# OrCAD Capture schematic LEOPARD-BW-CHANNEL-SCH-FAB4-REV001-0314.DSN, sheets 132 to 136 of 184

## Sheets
132 031_CPU1 - PCIE (2A-2D): size A3; title: CPU0 - PCIE (2A-2D); note: LEOPARD MAIN BOARD
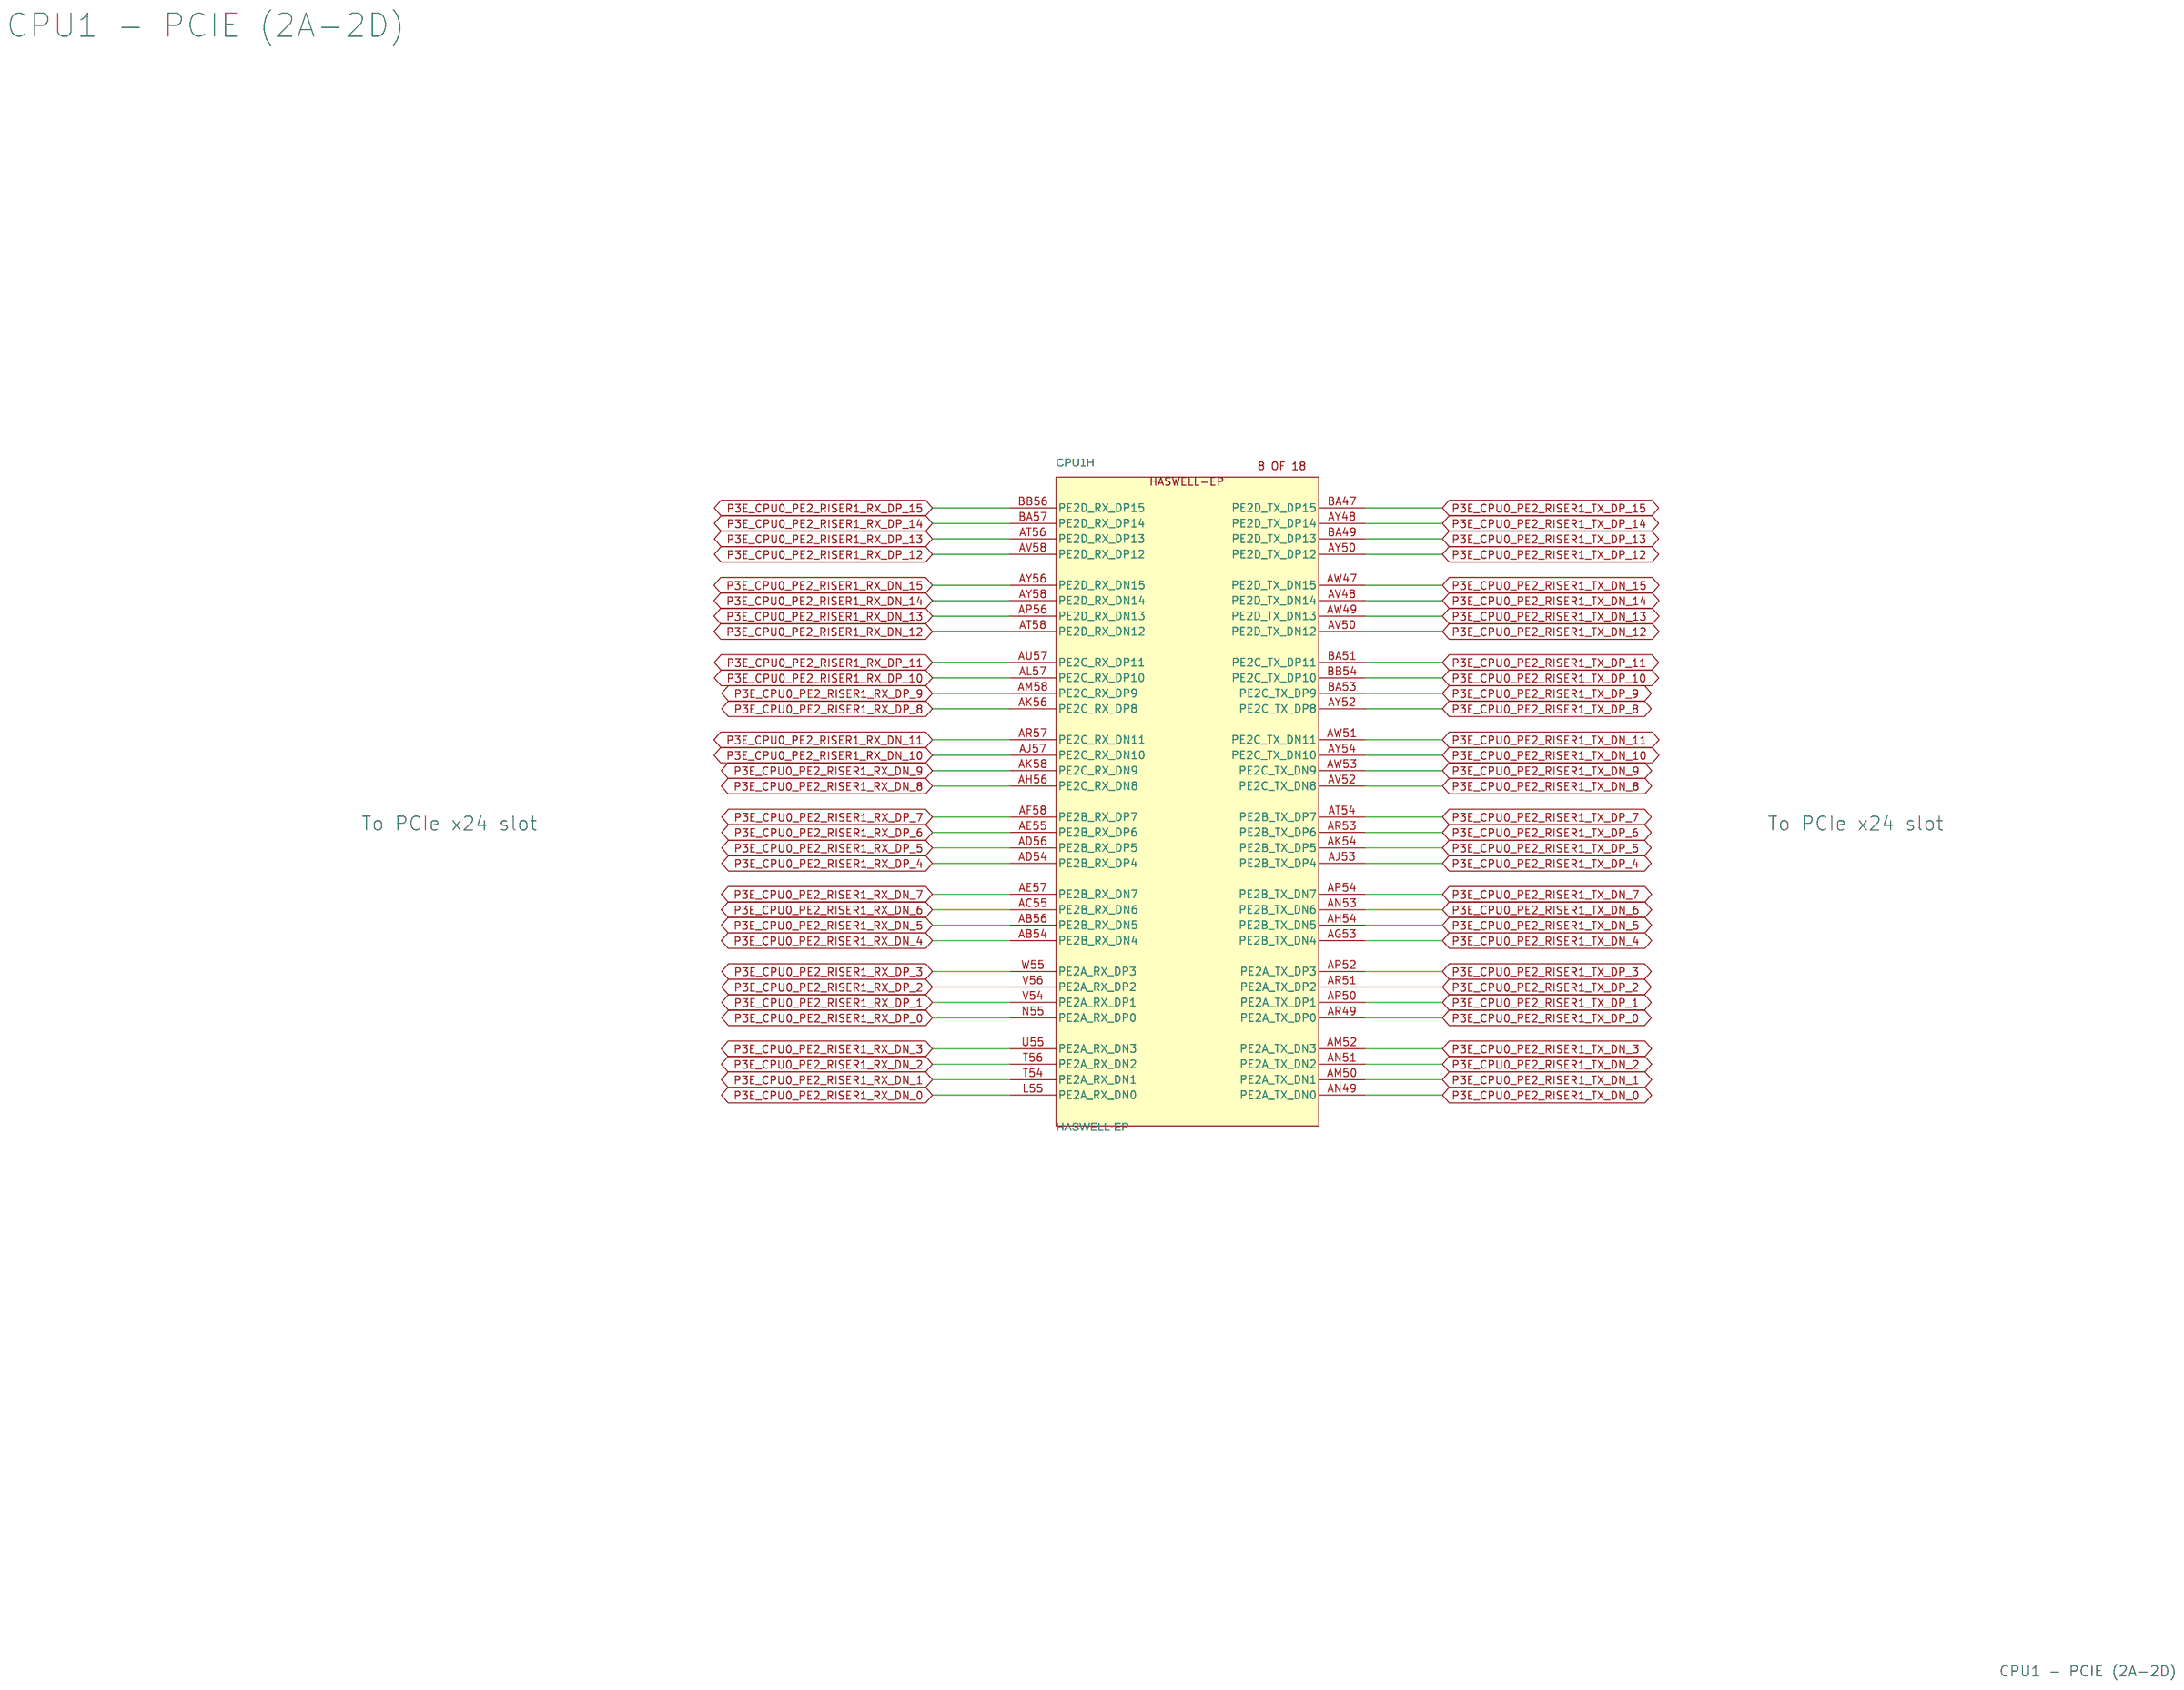
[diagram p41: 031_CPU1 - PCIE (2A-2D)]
133 030_CPU1 - DMI & PCIE (1A-1B): size A3; title: CPU1 - DMI & PCIE (1A-1B)
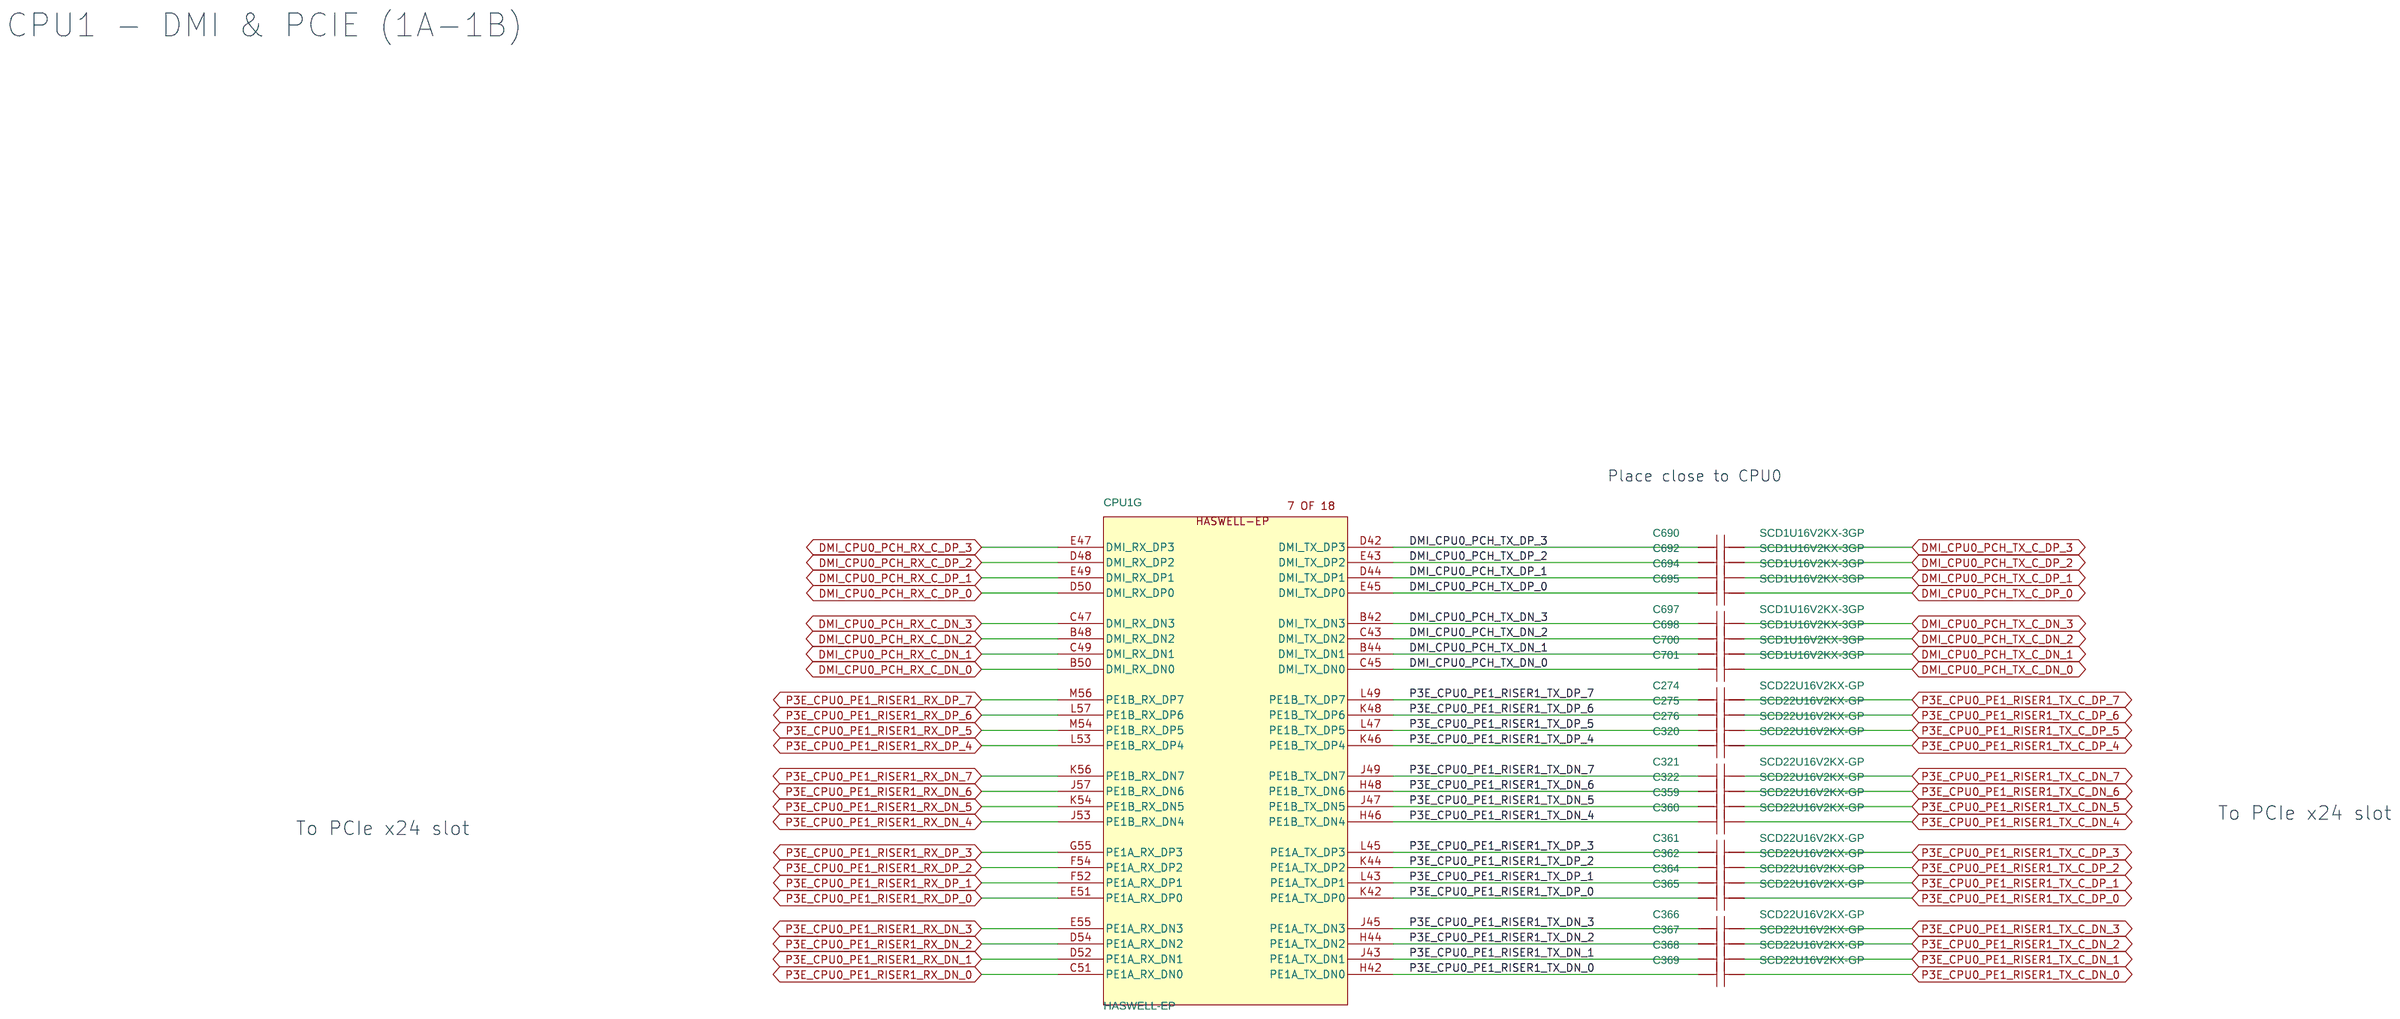
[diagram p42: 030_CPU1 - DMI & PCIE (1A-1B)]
134 029_CPU1 - DDR4 (CHANNEL D): size A3; title: CPU0 - DDR4 (CHANNEL D)
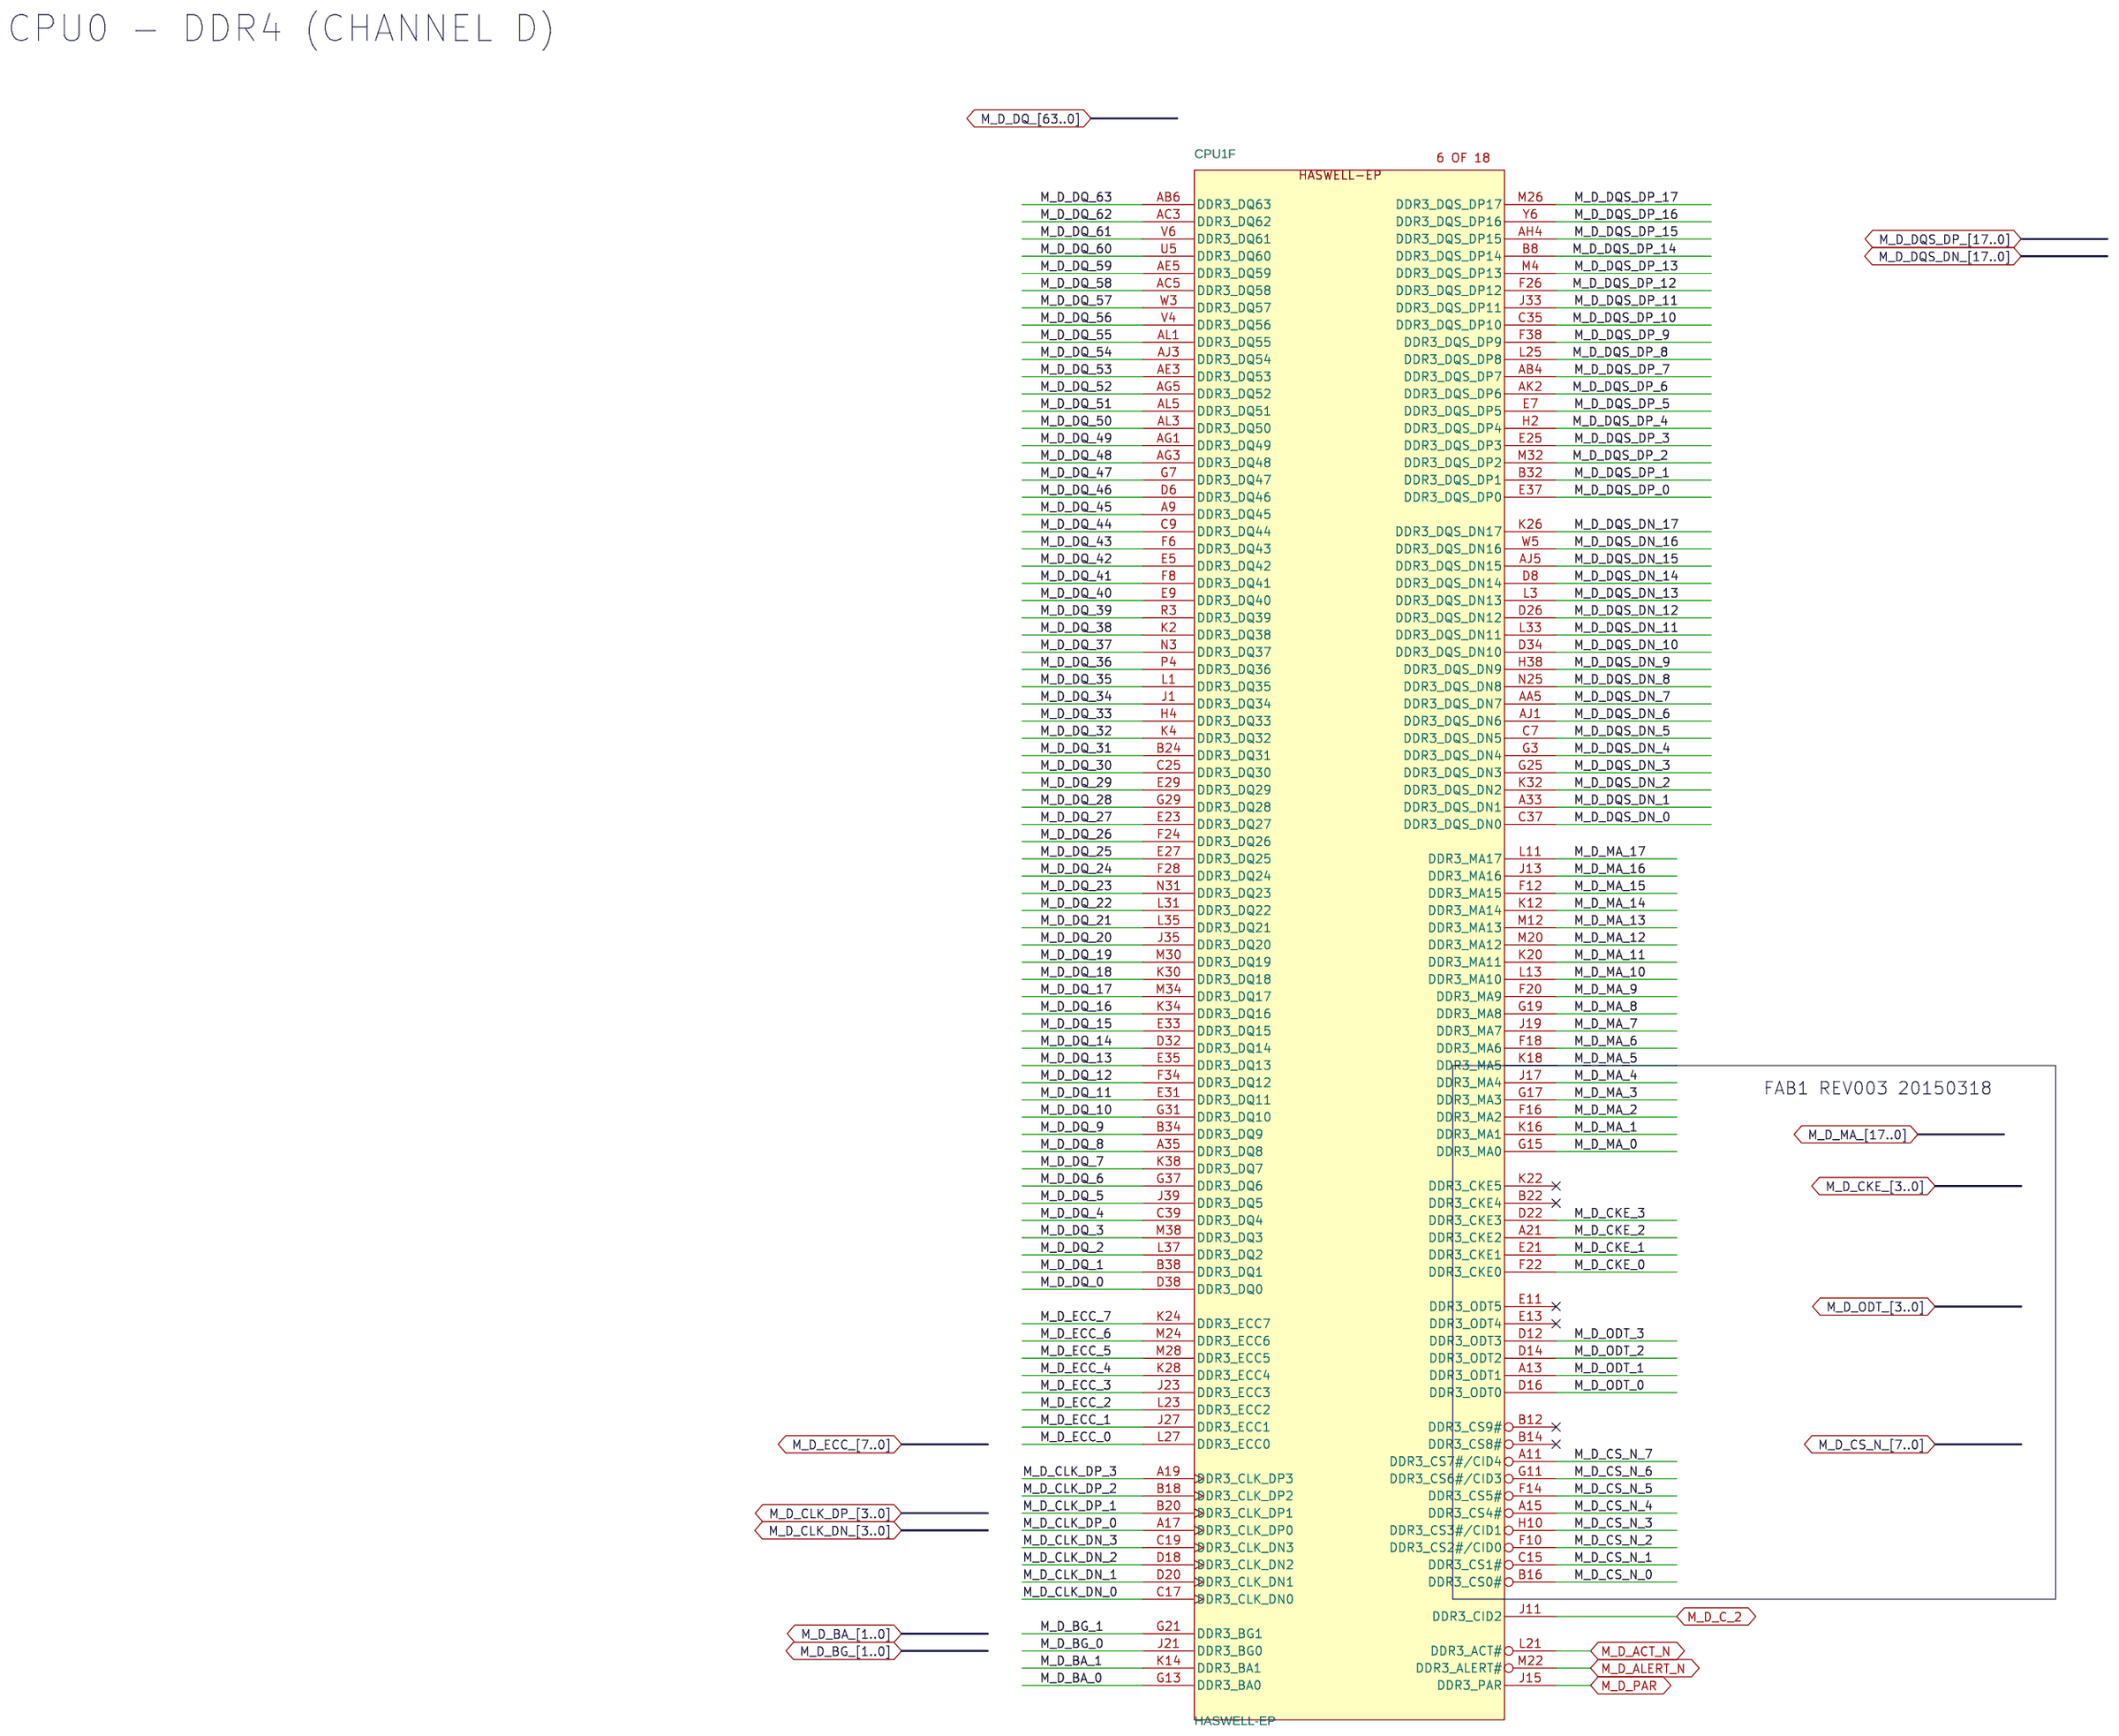
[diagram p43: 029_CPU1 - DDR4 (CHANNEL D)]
135 028_CPU1 - DDR4 (CHANNEL C): size A3; title: CPU1 - DDR4 (CAHANNEL C)
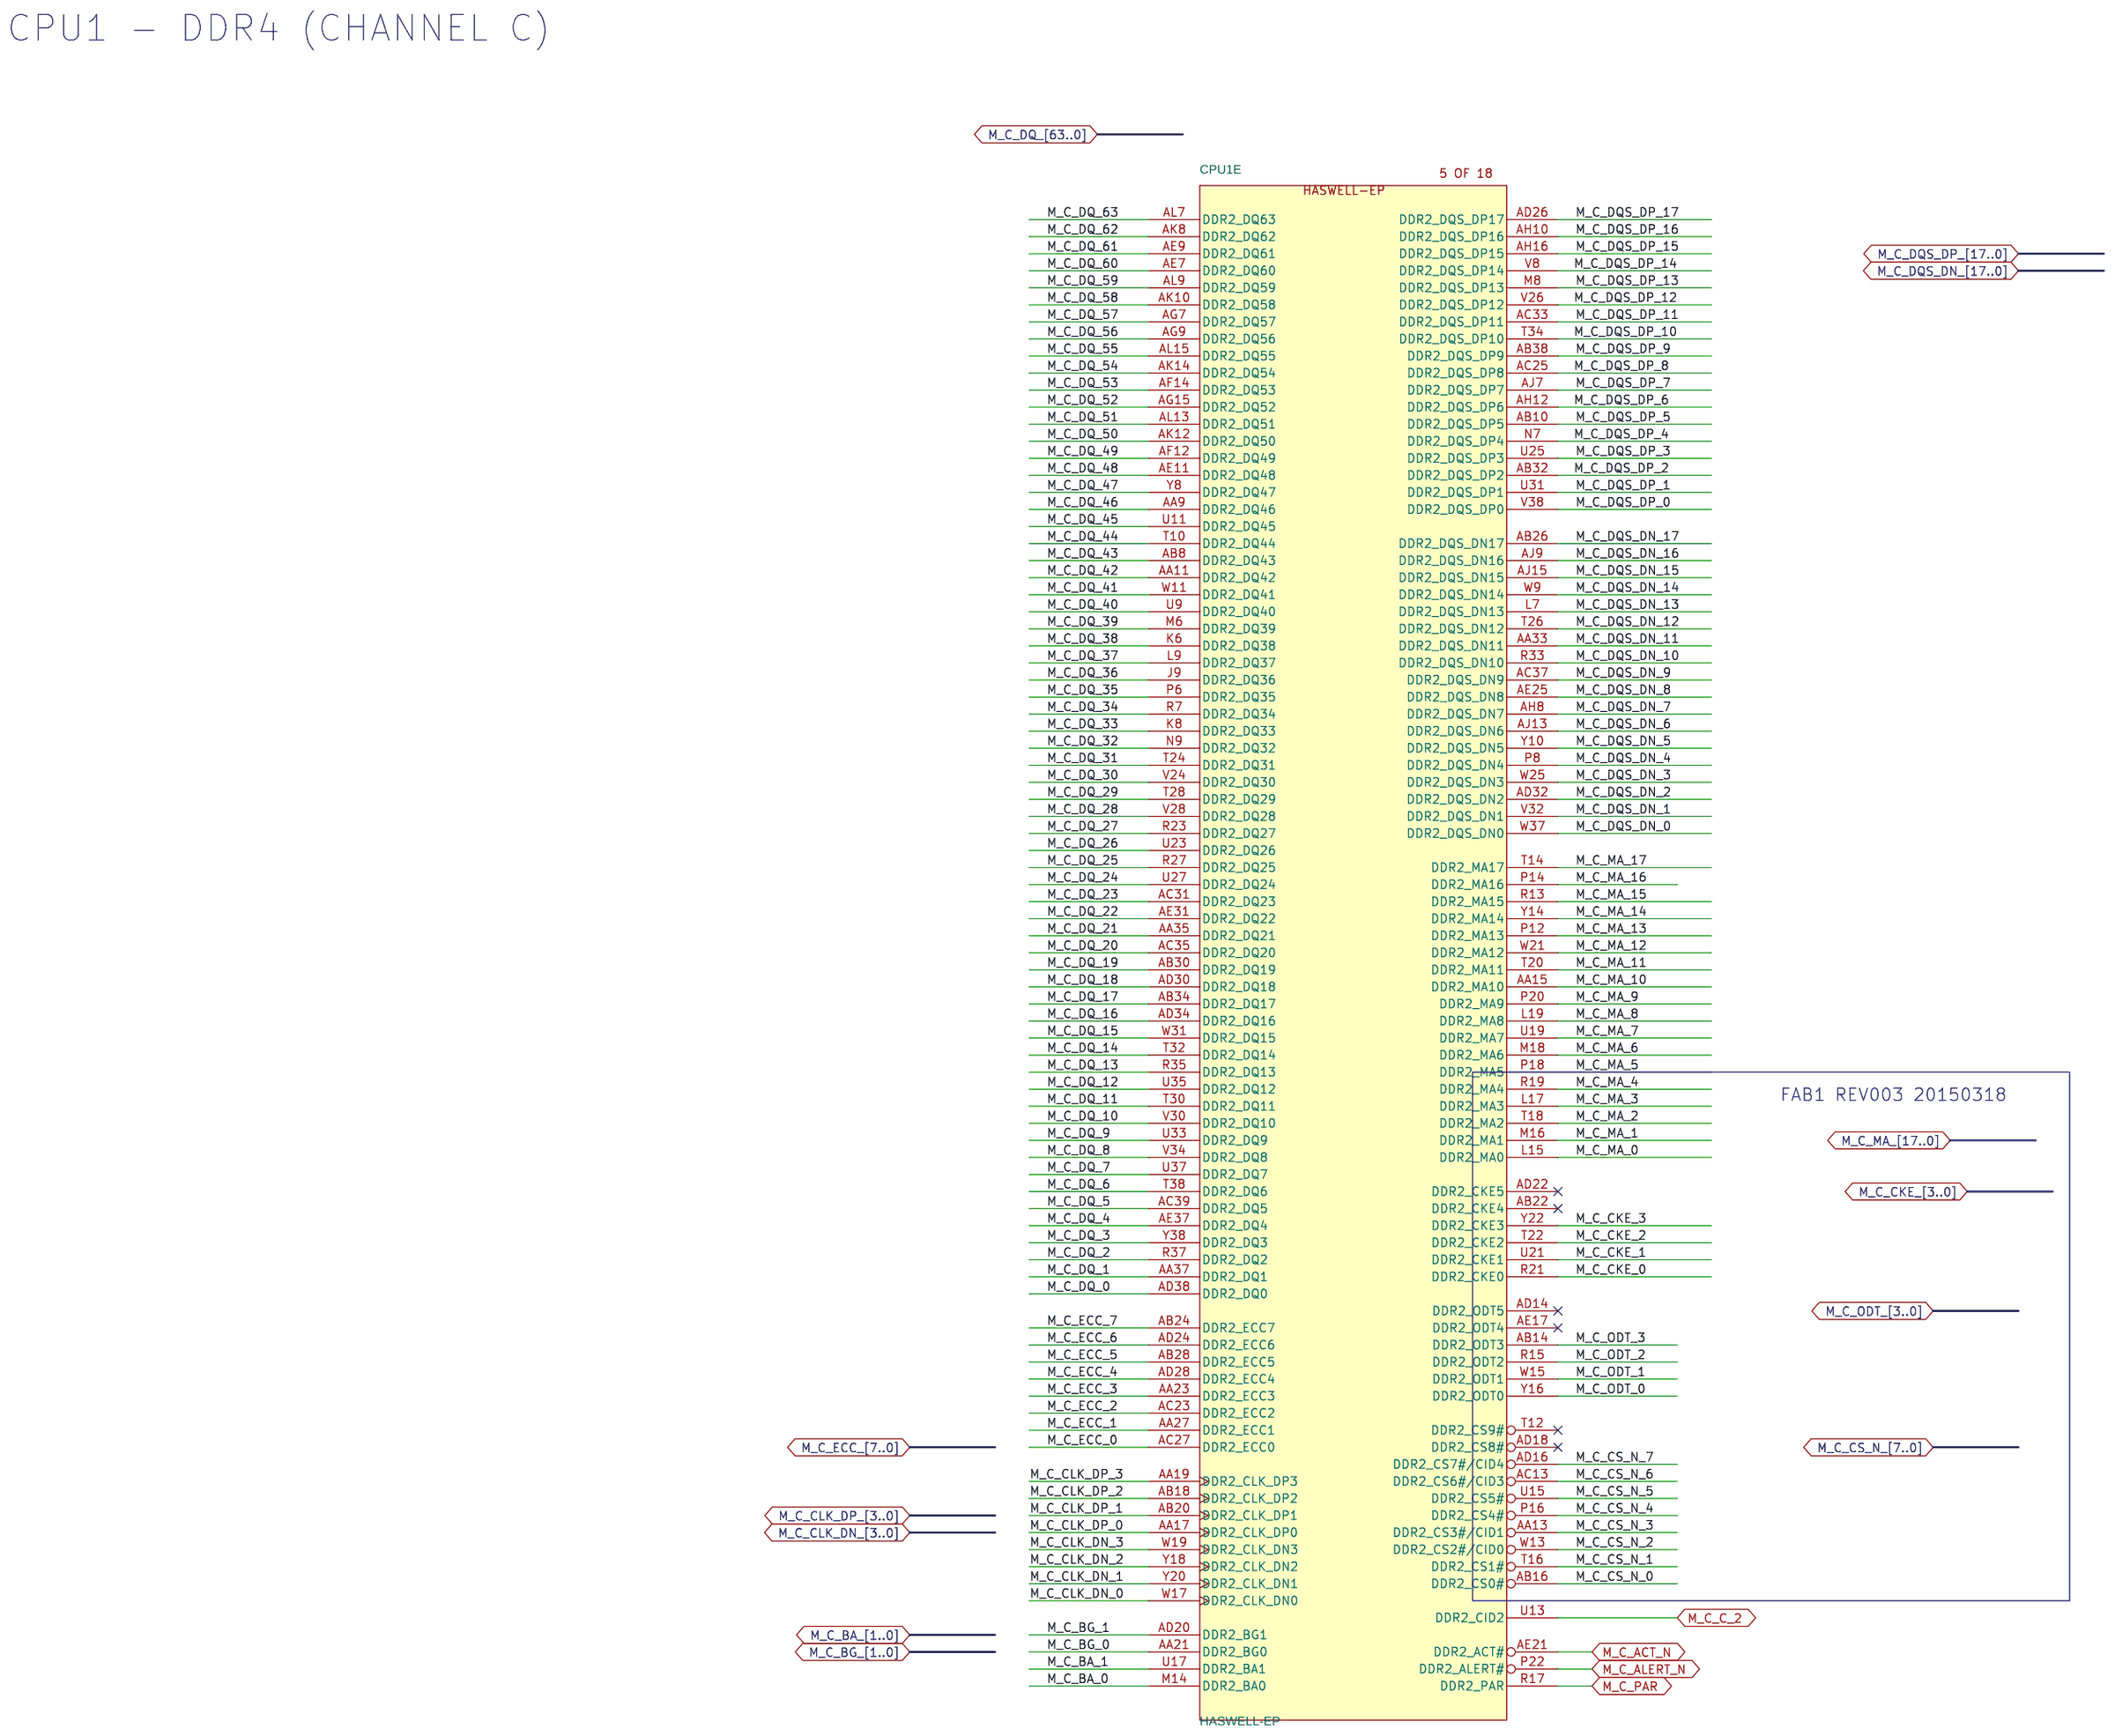
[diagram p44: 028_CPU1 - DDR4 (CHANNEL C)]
136 027_CPU1 - DDR4 (CHANNEL B): size A3; title: CPU0 - DDR4 (CHANNEL B)
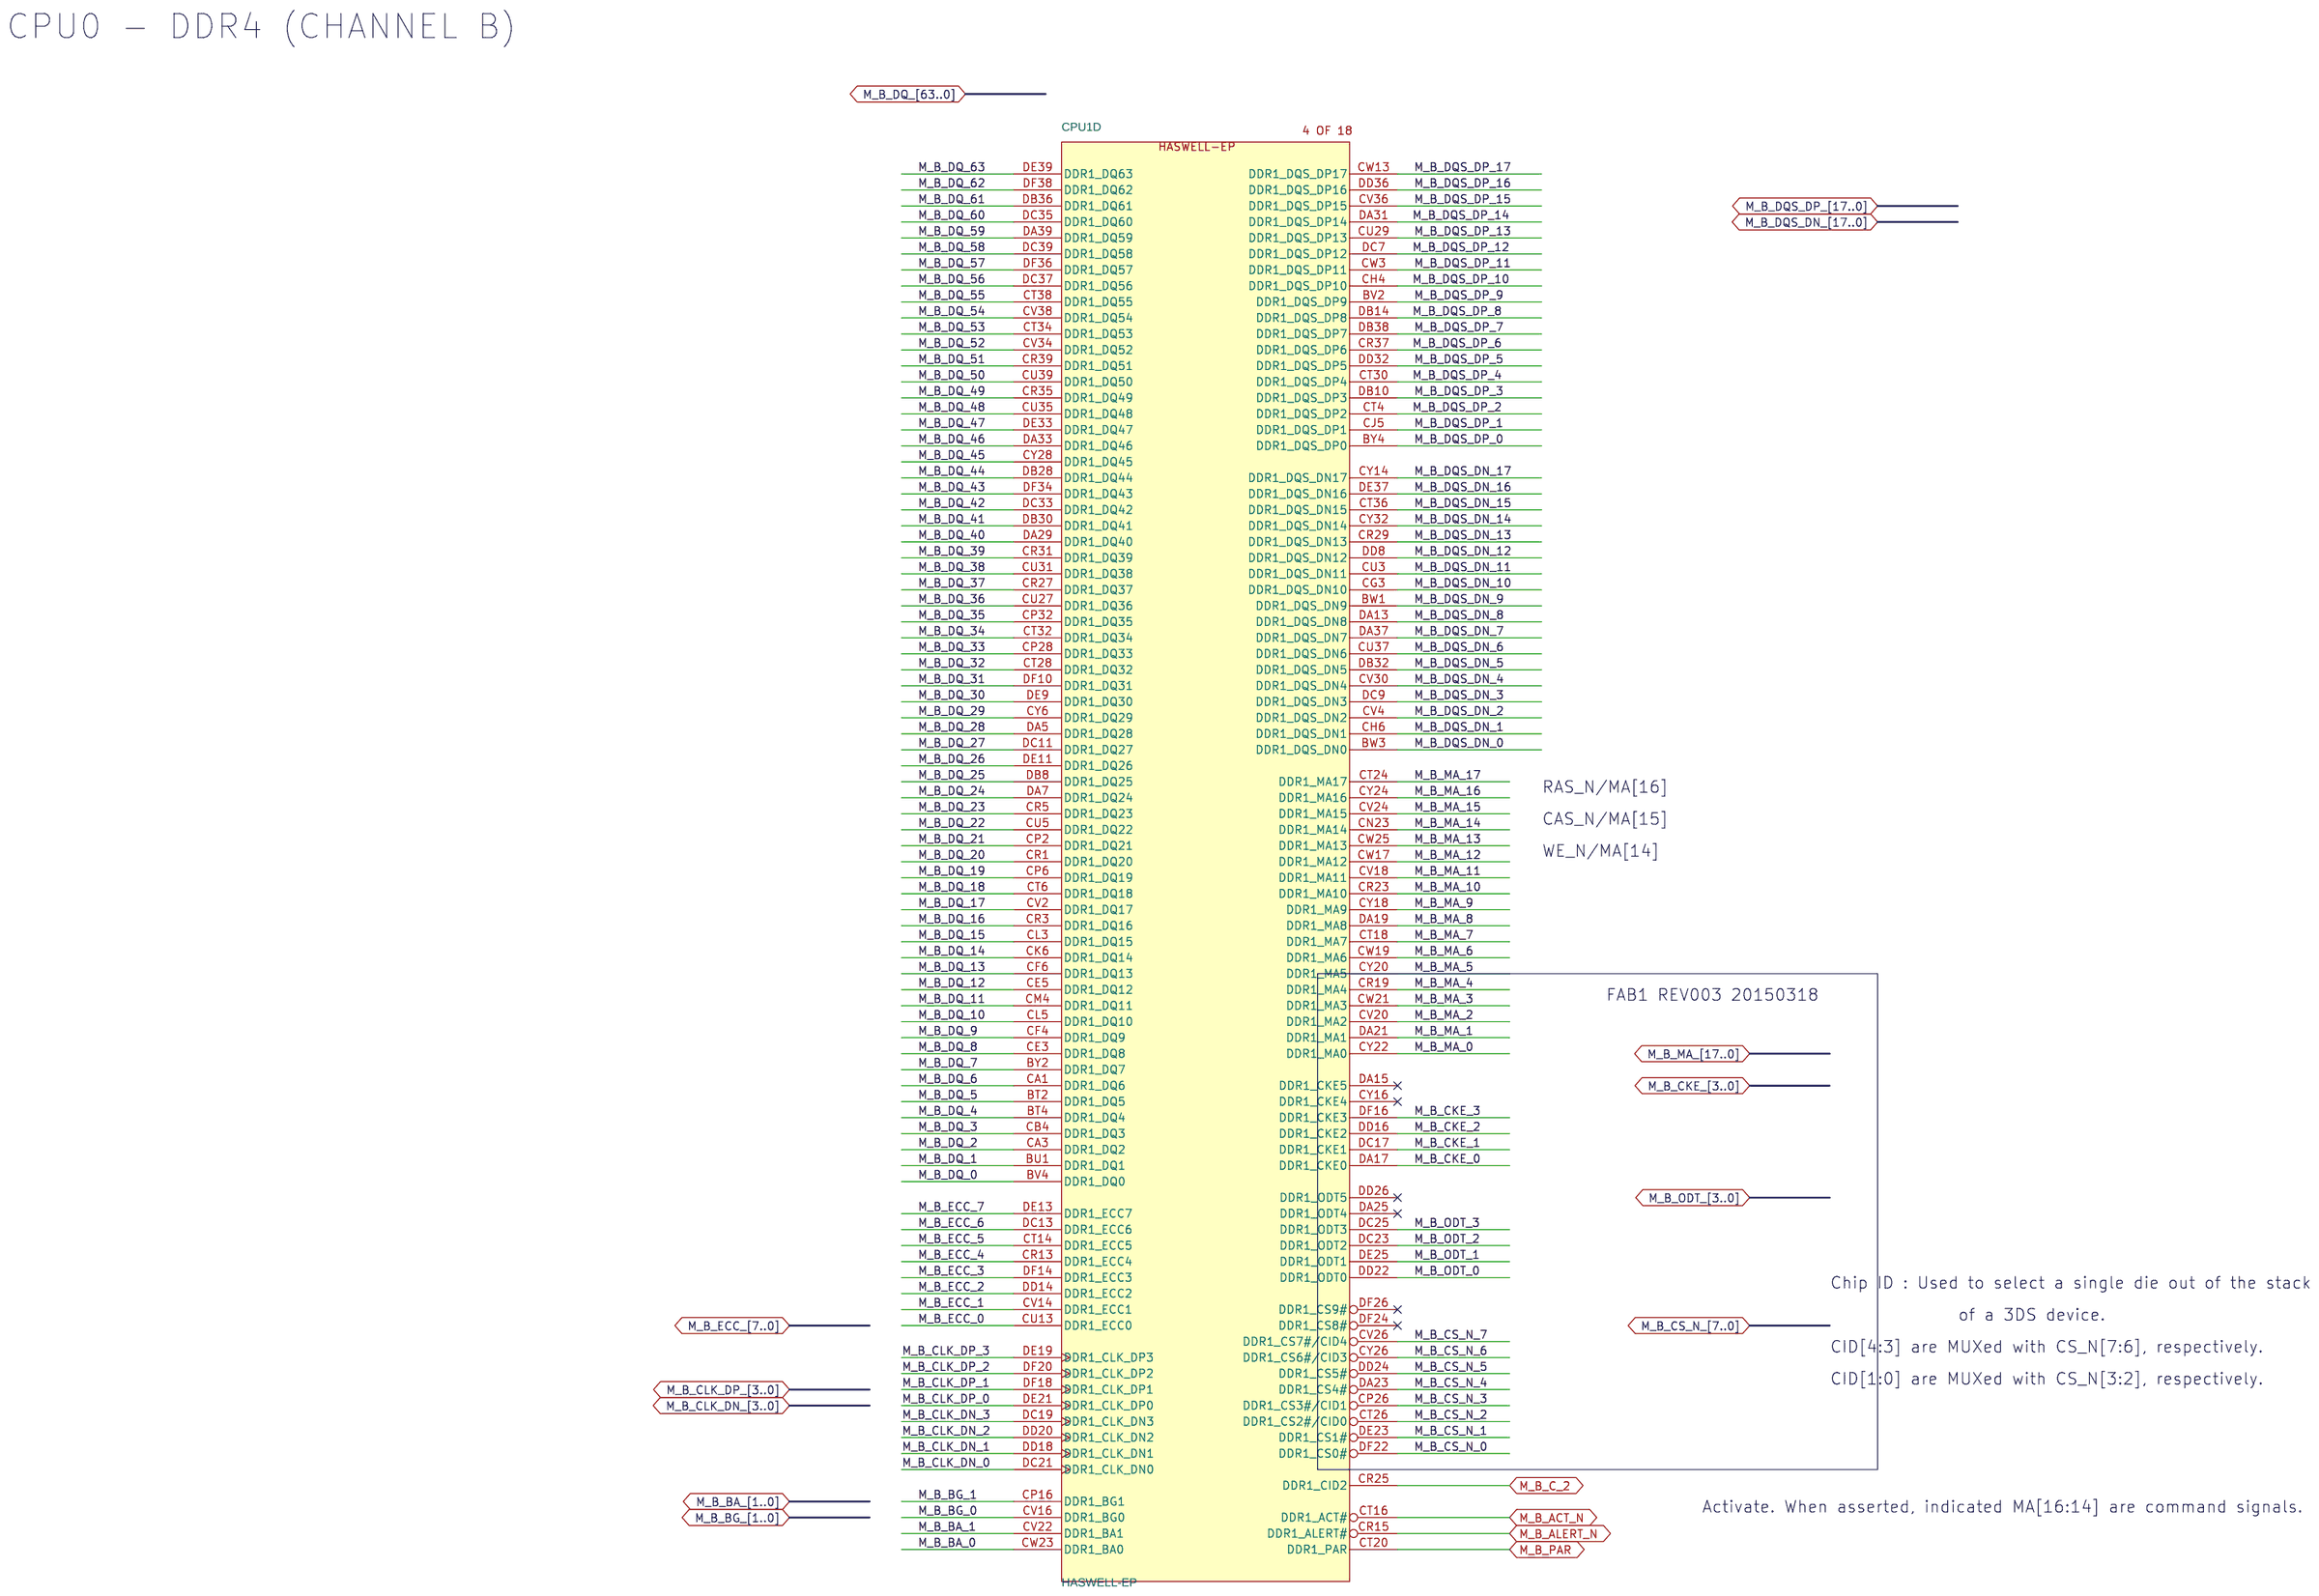
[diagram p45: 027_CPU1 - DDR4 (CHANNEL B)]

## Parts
sheet 030_CPU1 - DMI & PCIE (1A-1B)
C274  SCD22U16V2KX-GP  [C402H22]
C275  SCD22U16V2KX-GP  [C402H22]
C276  SCD22U16V2KX-GP  [C402H22]
C320  SCD22U16V2KX-GP  [C402H22]
C321  SCD22U16V2KX-GP  [C402H22]
C322  SCD22U16V2KX-GP  [C402H22]
C359  SCD22U16V2KX-GP  [C402H22]
C360  SCD22U16V2KX-GP  [C402H22]
C361  SCD22U16V2KX-GP  [C402H22]
C362  SCD22U16V2KX-GP  [C402H22]
C364  SCD22U16V2KX-GP  [C402H22]
C365  SCD22U16V2KX-GP  [C402H22]
C366  SCD22U16V2KX-GP  [C402H22]
C367  SCD22U16V2KX-GP  [C402H22]
C368  SCD22U16V2KX-GP  [C402H22]
C369  SCD22U16V2KX-GP  [C402H22]
C690  SCD1U16V2KX-3GP  [C402H22]
C692  SCD1U16V2KX-3GP  [C402H22]
C694  SCD1U16V2KX-3GP  [C402H22]
C695  SCD1U16V2KX-3GP  [C402H22]
C697  SCD1U16V2KX-3GP  [C402H22]
C698  SCD1U16V2KX-3GP  [C402H22]
C700  SCD1U16V2KX-3GP  [C402H22]
C701  SCD1U16V2KX-3GP  [C402H22]
sheet 035_CPU1 - VCCIN & VDDQ
CPU1  HASWELL-EP  [SKT-LGA2011M6151-1H298]  (sections A,B,C,D,E,F,G,H,I,J,K,L,M,N,O,P,Q,R)

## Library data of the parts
C274-C276 C320-C322 C359-C362 C364-C369 = SCD22U16V2KX-GP: CHIP CAP C 0.22U 16V K0402 X7R; GREENDFACTOR: R2_SA;HF_SA;G_SA;; Part Number: 78.22421.2FL; Part Type: SMD-BCG4; SPEC: http://wpqssvr.wistron.com.tw:7001/wpqs/servlet/COM.qpart.Attachment?PartNumber=78.22421.2FL
C690 C692 C694 C695 C697 C698 C700 C701 = SCD1U16V2KX-3GP: CHIP CAP C 0.1U 16V K0402 X7R; Category: CPU0; GREENDFACTOR: R_SA;HF_SA;G_SA;; Part Number: 78.10421.2FL; Quotation: 13_8; Type: SMD
CPU1 = HASWELL-EP: SKT CPU LGA 2011P AZIF0001-P004C SMD; GREENDFACTOR: R2_C;; POP?: 62.10079.311; Package Type: SOCKET-G2; Part Number: 62.10079.261; SPEC: http://wpqssvr.wistron.com.tw:7001/wpqs/servlet/COM.qpart.Attachment?PartNumber=62.10079.261

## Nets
DMI_CPU0_PCH_RX_C_DN_0: CPU1.B50(DMI_RX_DN0) ; also on sheet 92
DMI_CPU0_PCH_RX_C_DN_1: CPU1.C49(DMI_RX_DN1) ; also on sheet 92
DMI_CPU0_PCH_RX_C_DN_2: CPU1.B48(DMI_RX_DN2) ; also on sheet 92
DMI_CPU0_PCH_RX_C_DN_3: CPU1.C47(DMI_RX_DN3) ; also on sheet 92
DMI_CPU0_PCH_RX_C_DP_0: CPU1.D50(DMI_RX_DP0) ; also on sheet 92
DMI_CPU0_PCH_RX_C_DP_1: CPU1.E49(DMI_RX_DP1) ; also on sheet 92
DMI_CPU0_PCH_RX_C_DP_2: CPU1.D48(DMI_RX_DP2) ; also on sheet 92
DMI_CPU0_PCH_RX_C_DP_3: CPU1.E47(DMI_RX_DP3) ; also on sheet 92
DMI_CPU0_PCH_TX_C_DN_0: C701.2 ; also on sheet 92
DMI_CPU0_PCH_TX_C_DN_1: C700.2 ; also on sheet 92
DMI_CPU0_PCH_TX_C_DN_2: C698.2 ; also on sheet 92
DMI_CPU0_PCH_TX_C_DN_3: C697.2 ; also on sheet 92
DMI_CPU0_PCH_TX_C_DP_0: C695.2 ; also on sheet 92
DMI_CPU0_PCH_TX_C_DP_1: C694.2 ; also on sheet 92
DMI_CPU0_PCH_TX_C_DP_2: C692.2 ; also on sheet 92
DMI_CPU0_PCH_TX_C_DP_3: C690.2 ; also on sheet 92
DMI_CPU0_PCH_TX_DN_0: C701.1 CPU1.C45(DMI_TX_DN0)
DMI_CPU0_PCH_TX_DN_1: C700.1 CPU1.B44(DMI_TX_DN1)
DMI_CPU0_PCH_TX_DN_2: C698.1 CPU1.C43(DMI_TX_DN2)
DMI_CPU0_PCH_TX_DN_3: C697.1 CPU1.B42(DMI_TX_DN3)
DMI_CPU0_PCH_TX_DP_0: C695.1 CPU1.E45(DMI_TX_DP0)
DMI_CPU0_PCH_TX_DP_1: C694.1 CPU1.D44(DMI_TX_DP1)
DMI_CPU0_PCH_TX_DP_2: C692.1 CPU1.E43(DMI_TX_DP2)
DMI_CPU0_PCH_TX_DP_3: C690.1 CPU1.D42(DMI_TX_DP3)
M_B_ACT_N: CPU1.CT16(DDR1_ACT#) ; also on sheet 116 117
M_B_ALERT_N: CPU1.CR15(DDR1_ALERT#) ; also on sheet 116 117
M_B_BA_0: CPU1.CW23(DDR1_BA0) ; also on sheet 116 117
M_B_BA_1: CPU1.CV22(DDR1_BA1) ; also on sheet 116 117
M_B_BG_0: CPU1.CV16(DDR1_BG0) ; also on sheet 116 117
M_B_BG_1: CPU1.CP16(DDR1_BG1) ; also on sheet 116 117
M_B_C_2: CPU1.CR25(DDR1_CID2) ; also on sheet 116 117
M_B_CKE_0: CPU1.DA17(DDR1_CKE0) ; also on sheet 117
M_B_CKE_1: CPU1.DC17(DDR1_CKE1) ; also on sheet 117
M_B_CKE_2: CPU1.DD16(DDR1_CKE2) ; also on sheet 116
M_B_CKE_3: CPU1.DF16(DDR1_CKE3) ; also on sheet 116
M_B_CLK_DN_0: CPU1.DC21(DDR1_CLK_DN0) ; also on sheet 117
M_B_CLK_DN_1: CPU1.DD18(DDR1_CLK_DN1) ; also on sheet 116
M_B_CLK_DN_2: CPU1.DD20(DDR1_CLK_DN2) ; also on sheet 117
M_B_CLK_DN_3: CPU1.DC19(DDR1_CLK_DN3) ; also on sheet 116
M_B_CLK_DP_0: CPU1.DE21(DDR1_CLK_DP0) ; also on sheet 117
M_B_CLK_DP_1: CPU1.DF18(DDR1_CLK_DP1) ; also on sheet 116
M_B_CLK_DP_2: CPU1.DF20(DDR1_CLK_DP2) ; also on sheet 117
M_B_CLK_DP_3: CPU1.DE19(DDR1_CLK_DP3) ; also on sheet 116
M_B_CS_N_0: CPU1.DF22(DDR1_CS0#) ; also on sheet 117
M_B_CS_N_1: CPU1.DE23(DDR1_CS1#) ; also on sheet 117
M_B_CS_N_2: CPU1.CT26(DDR1_CS2#/CID0) ; also on sheet 117
M_B_CS_N_3: CPU1.CP26(DDR1_CS3#/CID1) ; also on sheet 117
M_B_CS_N_4: CPU1.DA23(DDR1_CS4#) ; also on sheet 116
M_B_CS_N_5: CPU1.DD24(DDR1_CS5#) ; also on sheet 116
M_B_CS_N_6: CPU1.CY26(DDR1_CS6#/CID3) ; also on sheet 116
M_B_CS_N_7: CPU1.CV26(DDR1_CS7#/CID4) ; also on sheet 116
M_B_DQ_0: CPU1.BV4(DDR1_DQ0) ; also on sheet 116 117
M_B_DQ_1: CPU1.BU1(DDR1_DQ1) ; also on sheet 116 117
M_B_DQ_2: CPU1.CA3(DDR1_DQ2) ; also on sheet 116 117
M_B_DQ_3: CPU1.CB4(DDR1_DQ3) ; also on sheet 116 117
M_B_DQ_4: CPU1.BT4(DDR1_DQ4) ; also on sheet 116 117
M_B_DQ_5: CPU1.BT2(DDR1_DQ5) ; also on sheet 116 117
M_B_DQ_6: CPU1.CA1(DDR1_DQ6) ; also on sheet 116 117
M_B_DQ_7: CPU1.BY2(DDR1_DQ7) ; also on sheet 116 117
M_B_DQ_8: CPU1.CE3(DDR1_DQ8) ; also on sheet 116 117
M_B_DQ_9: CPU1.CF4(DDR1_DQ9) ; also on sheet 116 117
M_B_DQ_10: CPU1.CL5(DDR1_DQ10) ; also on sheet 116 117
M_B_DQ_11: CPU1.CM4(DDR1_DQ11) ; also on sheet 116 117
M_B_DQ_12: CPU1.CE5(DDR1_DQ12) ; also on sheet 116 117
M_B_DQ_13: CPU1.CF6(DDR1_DQ13) ; also on sheet 116 117
M_B_DQ_14: CPU1.CK6(DDR1_DQ14) ; also on sheet 116 117
M_B_DQ_15: CPU1.CL3(DDR1_DQ15) ; also on sheet 116 117
M_B_DQ_16: CPU1.CR3(DDR1_DQ16) ; also on sheet 116 117
M_B_DQ_17: CPU1.CV2(DDR1_DQ17) ; also on sheet 116 117
M_B_DQ_18: CPU1.CT6(DDR1_DQ18) ; also on sheet 116 117
M_B_DQ_19: CPU1.CP6(DDR1_DQ19) ; also on sheet 116 117
M_B_DQ_20: CPU1.CR1(DDR1_DQ20) ; also on sheet 116 117
M_B_DQ_21: CPU1.CP2(DDR1_DQ21) ; also on sheet 116 117
M_B_DQ_22: CPU1.CU5(DDR1_DQ22) ; also on sheet 116 117
M_B_DQ_23: CPU1.CR5(DDR1_DQ23) ; also on sheet 116 117
M_B_DQ_24: CPU1.DA7(DDR1_DQ24) ; also on sheet 116 117
M_B_DQ_25: CPU1.DB8(DDR1_DQ25) ; also on sheet 116 117
M_B_DQ_26: CPU1.DE11(DDR1_DQ26) ; also on sheet 116 117
M_B_DQ_27: CPU1.DC11(DDR1_DQ27) ; also on sheet 116 117
M_B_DQ_28: CPU1.DA5(DDR1_DQ28) ; also on sheet 116 117
M_B_DQ_29: CPU1.CY6(DDR1_DQ29) ; also on sheet 116 117
M_B_DQ_30: CPU1.DE9(DDR1_DQ30) ; also on sheet 116 117
M_B_DQ_31: CPU1.DF10(DDR1_DQ31) ; also on sheet 116 117
M_B_DQ_32: CPU1.CT28(DDR1_DQ32) ; also on sheet 116 117
M_B_DQ_33: CPU1.CP28(DDR1_DQ33) ; also on sheet 116 117
M_B_DQ_34: CPU1.CT32(DDR1_DQ34) ; also on sheet 116 117
M_B_DQ_35: CPU1.CP32(DDR1_DQ35) ; also on sheet 116 117
M_B_DQ_36: CPU1.CU27(DDR1_DQ36) ; also on sheet 116 117
M_B_DQ_37: CPU1.CR27(DDR1_DQ37) ; also on sheet 116 117
M_B_DQ_38: CPU1.CU31(DDR1_DQ38) ; also on sheet 116 117
M_B_DQ_39: CPU1.CR31(DDR1_DQ39) ; also on sheet 116 117
M_B_DQ_40: CPU1.DA29(DDR1_DQ40) ; also on sheet 116 117
M_B_DQ_41: CPU1.DB30(DDR1_DQ41) ; also on sheet 116 117
M_B_DQ_42: CPU1.DC33(DDR1_DQ42) ; also on sheet 116 117
M_B_DQ_43: CPU1.DF34(DDR1_DQ43) ; also on sheet 116 117
M_B_DQ_44: CPU1.DB28(DDR1_DQ44) ; also on sheet 116 117
M_B_DQ_45: CPU1.CY28(DDR1_DQ45) ; also on sheet 116 117
M_B_DQ_46: CPU1.DA33(DDR1_DQ46) ; also on sheet 116 117
M_B_DQ_47: CPU1.DE33(DDR1_DQ47) ; also on sheet 116 117
M_B_DQ_48: CPU1.CU35(DDR1_DQ48) ; also on sheet 116 117
M_B_DQ_49: CPU1.CR35(DDR1_DQ49) ; also on sheet 116 117
M_B_DQ_50: CPU1.CU39(DDR1_DQ50) ; also on sheet 116 117
M_B_DQ_51: CPU1.CR39(DDR1_DQ51) ; also on sheet 116 117
M_B_DQ_52: CPU1.CV34(DDR1_DQ52) ; also on sheet 116 117
M_B_DQ_53: CPU1.CT34(DDR1_DQ53) ; also on sheet 116 117
M_B_DQ_54: CPU1.CV38(DDR1_DQ54) ; also on sheet 116 117
M_B_DQ_55: CPU1.CT38(DDR1_DQ55) ; also on sheet 116 117
M_B_DQ_56: CPU1.DC37(DDR1_DQ56) ; also on sheet 116 117
M_B_DQ_57: CPU1.DF36(DDR1_DQ57) ; also on sheet 116 117
M_B_DQ_58: CPU1.DC39(DDR1_DQ58) ; also on sheet 116 117
M_B_DQ_59: CPU1.DA39(DDR1_DQ59) ; also on sheet 116 117
M_B_DQ_60: CPU1.DC35(DDR1_DQ60) ; also on sheet 116 117
M_B_DQ_61: CPU1.DB36(DDR1_DQ61) ; also on sheet 116 117
M_B_DQ_62: CPU1.DF38(DDR1_DQ62) ; also on sheet 116 117
M_B_DQ_63: CPU1.DE39(DDR1_DQ63) ; also on sheet 116 117
M_B_DQS_DN_0: CPU1.BW3(DDR1_DQS_DN0) ; also on sheet 116 117
M_B_DQS_DN_1: CPU1.CH6(DDR1_DQS_DN1) ; also on sheet 116 117
M_B_DQS_DN_2: CPU1.CV4(DDR1_DQS_DN2) ; also on sheet 116 117
M_B_DQS_DN_3: CPU1.DC9(DDR1_DQS_DN3) ; also on sheet 116 117
M_B_DQS_DN_4: CPU1.CV30(DDR1_DQS_DN4) ; also on sheet 116 117
M_B_DQS_DN_5: CPU1.DB32(DDR1_DQS_DN5) ; also on sheet 116 117
M_B_DQS_DN_6: CPU1.CU37(DDR1_DQS_DN6) ; also on sheet 116 117
M_B_DQS_DN_7: CPU1.DA37(DDR1_DQS_DN7) ; also on sheet 116 117
M_B_DQS_DN_8: CPU1.DA13(DDR1_DQS_DN8) ; also on sheet 116 117
M_B_DQS_DN_9: CPU1.BW1(DDR1_DQS_DN9) ; also on sheet 116 117
M_B_DQS_DN_10: CPU1.CG3(DDR1_DQS_DN10) ; also on sheet 116 117
M_B_DQS_DN_11: CPU1.CU3(DDR1_DQS_DN11) ; also on sheet 116 117
M_B_DQS_DN_12: CPU1.DD8(DDR1_DQS_DN12) ; also on sheet 116 117
M_B_DQS_DN_13: CPU1.CR29(DDR1_DQS_DN13) ; also on sheet 116 117
M_B_DQS_DN_14: CPU1.CY32(DDR1_DQS_DN14) ; also on sheet 116 117
M_B_DQS_DN_15: CPU1.CT36(DDR1_DQS_DN15) ; also on sheet 116 117
M_B_DQS_DN_16: CPU1.DE37(DDR1_DQS_DN16) ; also on sheet 116 117
M_B_DQS_DN_17: CPU1.CY14(DDR1_DQS_DN17) ; also on sheet 116 117
M_B_DQS_DP_0: CPU1.BY4(DDR1_DQS_DP0) ; also on sheet 116 117
M_B_DQS_DP_1: CPU1.CJ5(DDR1_DQS_DP1) ; also on sheet 116 117
M_B_DQS_DP_2: CPU1.CT4(DDR1_DQS_DP2) ; also on sheet 116 117
M_B_DQS_DP_3: CPU1.DB10(DDR1_DQS_DP3) ; also on sheet 116 117
M_B_DQS_DP_4: CPU1.CT30(DDR1_DQS_DP4) ; also on sheet 116 117
M_B_DQS_DP_5: CPU1.DD32(DDR1_DQS_DP5) ; also on sheet 116 117
M_B_DQS_DP_6: CPU1.CR37(DDR1_DQS_DP6) ; also on sheet 116 117
M_B_DQS_DP_7: CPU1.DB38(DDR1_DQS_DP7) ; also on sheet 116 117
M_B_DQS_DP_8: CPU1.DB14(DDR1_DQS_DP8) ; also on sheet 116 117
M_B_DQS_DP_9: CPU1.BV2(DDR1_DQS_DP9) ; also on sheet 116 117
M_B_DQS_DP_10: CPU1.CH4(DDR1_DQS_DP10) ; also on sheet 116 117
M_B_DQS_DP_11: CPU1.CW3(DDR1_DQS_DP11) ; also on sheet 116 117
M_B_DQS_DP_12: CPU1.DC7(DDR1_DQS_DP12) ; also on sheet 116 117
M_B_DQS_DP_13: CPU1.CU29(DDR1_DQS_DP13) ; also on sheet 116 117
M_B_DQS_DP_14: CPU1.DA31(DDR1_DQS_DP14) ; also on sheet 116 117
M_B_DQS_DP_15: CPU1.CV36(DDR1_DQS_DP15) ; also on sheet 116 117
M_B_DQS_DP_16: CPU1.DD36(DDR1_DQS_DP16) ; also on sheet 116 117
M_B_DQS_DP_17: CPU1.CW13(DDR1_DQS_DP17) ; also on sheet 116 117
M_B_ECC_0: CPU1.CU13(DDR1_ECC0) ; also on sheet 116 117
M_B_ECC_1: CPU1.CV14(DDR1_ECC1) ; also on sheet 116 117
M_B_ECC_2: CPU1.DD14(DDR1_ECC2) ; also on sheet 116 117
M_B_ECC_3: CPU1.DF14(DDR1_ECC3) ; also on sheet 116 117
M_B_ECC_4: CPU1.CR13(DDR1_ECC4) ; also on sheet 116 117
M_B_ECC_5: CPU1.CT14(DDR1_ECC5) ; also on sheet 116 117
M_B_ECC_6: CPU1.DC13(DDR1_ECC6) ; also on sheet 116 117
M_B_ECC_7: CPU1.DE13(DDR1_ECC7) ; also on sheet 116 117
M_B_MA_0: CPU1.CY22(DDR1_MA0) ; also on sheet 116 117
M_B_MA_1: CPU1.DA21(DDR1_MA1) ; also on sheet 116 117
M_B_MA_2: CPU1.CV20(DDR1_MA2) ; also on sheet 116 117
M_B_MA_3: CPU1.CW21(DDR1_MA3) ; also on sheet 116 117
M_B_MA_4: CPU1.CR19(DDR1_MA4) ; also on sheet 116 117
M_B_MA_5: CPU1.CY20(DDR1_MA5) ; also on sheet 116 117
M_B_MA_6: CPU1.CW19(DDR1_MA6) ; also on sheet 116 117
M_B_MA_7: CPU1.CT18(DDR1_MA7) ; also on sheet 116 117
M_B_MA_8: CPU1.DA19(DDR1_MA8) ; also on sheet 116 117
M_B_MA_9: CPU1.CY18(DDR1_MA9) ; also on sheet 116 117
M_B_MA_10: CPU1.CR23(DDR1_MA10) ; also on sheet 116 117
M_B_MA_11: CPU1.CV18(DDR1_MA11) ; also on sheet 116 117
M_B_MA_12: CPU1.CW17(DDR1_MA12) ; also on sheet 116 117
M_B_MA_13: CPU1.CW25(DDR1_MA13) ; also on sheet 116 117
M_B_MA_14: CPU1.CN23(DDR1_MA14) ; also on sheet 116 117
M_B_MA_15: CPU1.CV24(DDR1_MA15) ; also on sheet 116 117
M_B_MA_16: CPU1.CY24(DDR1_MA16) ; also on sheet 116 117
M_B_MA_17: CPU1.CT24(DDR1_MA17) ; also on sheet 116 117
M_B_ODT_0: CPU1.DD22(DDR1_ODT0) ; also on sheet 117
M_B_ODT_1: CPU1.DE25(DDR1_ODT1) ; also on sheet 117
M_B_ODT_2: CPU1.DC23(DDR1_ODT2) ; also on sheet 116
M_B_ODT_3: CPU1.DC25(DDR1_ODT3) ; also on sheet 116
M_B_PAR: CPU1.CT20(DDR1_PAR) ; also on sheet 116 117
M_C_ACT_N: CPU1.AE21(DDR2_ACT#) ; also on sheet 114 115
M_C_ALERT_N: CPU1.P22(DDR2_ALERT#) ; also on sheet 114 115
M_C_BA_0: CPU1.M14(DDR2_BA0) ; also on sheet 114 115
M_C_BA_1: CPU1.U17(DDR2_BA1) ; also on sheet 114 115
M_C_BG_0: CPU1.AA21(DDR2_BG0) ; also on sheet 114 115
M_C_BG_1: CPU1.AD20(DDR2_BG1) ; also on sheet 114 115
M_C_C_2: CPU1.U13(DDR2_CID2) ; also on sheet 114 115
M_C_CKE_0: CPU1.R21(DDR2_CKE0) ; also on sheet 115
M_C_CKE_1: CPU1.U21(DDR2_CKE1) ; also on sheet 115
M_C_CKE_2: CPU1.T22(DDR2_CKE2) ; also on sheet 114
M_C_CKE_3: CPU1.Y22(DDR2_CKE3) ; also on sheet 114
M_C_CLK_DN_0: CPU1.W17(DDR2_CLK_DN0) ; also on sheet 115
M_C_CLK_DN_1: CPU1.Y20(DDR2_CLK_DN1) ; also on sheet 114
M_C_CLK_DN_2: CPU1.Y18(DDR2_CLK_DN2) ; also on sheet 115
M_C_CLK_DN_3: CPU1.W19(DDR2_CLK_DN3) ; also on sheet 114
M_C_CLK_DP_0: CPU1.AA17(DDR2_CLK_DP0) ; also on sheet 115
M_C_CLK_DP_1: CPU1.AB20(DDR2_CLK_DP1) ; also on sheet 114
M_C_CLK_DP_2: CPU1.AB18(DDR2_CLK_DP2) ; also on sheet 115
M_C_CLK_DP_3: CPU1.AA19(DDR2_CLK_DP3) ; also on sheet 114
M_C_CS_N_0: CPU1.AB16(DDR2_CS0#) ; also on sheet 115
M_C_CS_N_1: CPU1.T16(DDR2_CS1#) ; also on sheet 115
M_C_CS_N_2: CPU1.W13(DDR2_CS2#/CID0) ; also on sheet 115
M_C_CS_N_3: CPU1.AA13(DDR2_CS3#/CID1) ; also on sheet 115
M_C_CS_N_4: CPU1.P16(DDR2_CS4#) ; also on sheet 114
M_C_CS_N_5: CPU1.U15(DDR2_CS5#) ; also on sheet 114
M_C_CS_N_6: CPU1.AC13(DDR2_CS6#/CID3) ; also on sheet 114
M_C_CS_N_7: CPU1.AD16(DDR2_CS7#/CID4) ; also on sheet 114
M_C_DQ_0: CPU1.AD38(DDR2_DQ0) ; also on sheet 114 115
M_C_DQ_1: CPU1.AA37(DDR2_DQ1) ; also on sheet 114 115
M_C_DQ_2: CPU1.R37(DDR2_DQ2) ; also on sheet 114 115
M_C_DQ_3: CPU1.Y38(DDR2_DQ3) ; also on sheet 114 115
M_C_DQ_4: CPU1.AE37(DDR2_DQ4) ; also on sheet 114 115
M_C_DQ_5: CPU1.AC39(DDR2_DQ5) ; also on sheet 114 115
M_C_DQ_6: CPU1.T38(DDR2_DQ6) ; also on sheet 114 115
M_C_DQ_7: CPU1.U37(DDR2_DQ7) ; also on sheet 114 115
M_C_DQ_8: CPU1.V34(DDR2_DQ8) ; also on sheet 114 115
M_C_DQ_9: CPU1.U33(DDR2_DQ9) ; also on sheet 114 115
M_C_DQ_10: CPU1.V30(DDR2_DQ10) ; also on sheet 114 115
M_C_DQ_11: CPU1.T30(DDR2_DQ11) ; also on sheet 114 115
M_C_DQ_12: CPU1.U35(DDR2_DQ12) ; also on sheet 114 115
M_C_DQ_13: CPU1.R35(DDR2_DQ13) ; also on sheet 114 115
M_C_DQ_14: CPU1.T32(DDR2_DQ14) ; also on sheet 114 115
M_C_DQ_15: CPU1.W31(DDR2_DQ15) ; also on sheet 114 115
M_C_DQ_16: CPU1.AD34(DDR2_DQ16) ; also on sheet 114 115
M_C_DQ_17: CPU1.AB34(DDR2_DQ17) ; also on sheet 114 115
M_C_DQ_18: CPU1.AD30(DDR2_DQ18) ; also on sheet 114 115
M_C_DQ_19: CPU1.AB30(DDR2_DQ19) ; also on sheet 114 115
M_C_DQ_20: CPU1.AC35(DDR2_DQ20) ; also on sheet 114 115
M_C_DQ_21: CPU1.AA35(DDR2_DQ21) ; also on sheet 114 115
M_C_DQ_22: CPU1.AE31(DDR2_DQ22) ; also on sheet 114 115
M_C_DQ_23: CPU1.AC31(DDR2_DQ23) ; also on sheet 114 115
M_C_DQ_24: CPU1.U27(DDR2_DQ24) ; also on sheet 114 115
M_C_DQ_25: CPU1.R27(DDR2_DQ25) ; also on sheet 114 115
M_C_DQ_26: CPU1.U23(DDR2_DQ26) ; also on sheet 114 115
M_C_DQ_27: CPU1.R23(DDR2_DQ27) ; also on sheet 114 115
M_C_DQ_28: CPU1.V28(DDR2_DQ28) ; also on sheet 114 115
M_C_DQ_29: CPU1.T28(DDR2_DQ29) ; also on sheet 114 115
M_C_DQ_30: CPU1.V24(DDR2_DQ30) ; also on sheet 114 115
M_C_DQ_31: CPU1.T24(DDR2_DQ31) ; also on sheet 114 115
M_C_DQ_32: CPU1.N9(DDR2_DQ32) ; also on sheet 114 115
M_C_DQ_33: CPU1.K8(DDR2_DQ33) ; also on sheet 114 115
M_C_DQ_34: CPU1.R7(DDR2_DQ34) ; also on sheet 114 115
M_C_DQ_35: CPU1.P6(DDR2_DQ35) ; also on sheet 114 115
M_C_DQ_36: CPU1.J9(DDR2_DQ36) ; also on sheet 114 115
M_C_DQ_37: CPU1.L9(DDR2_DQ37) ; also on sheet 114 115
M_C_DQ_38: CPU1.K6(DDR2_DQ38) ; also on sheet 114 115
M_C_DQ_39: CPU1.M6(DDR2_DQ39) ; also on sheet 114 115
M_C_DQ_40: CPU1.U9(DDR2_DQ40) ; also on sheet 114 115
M_C_DQ_41: CPU1.W11(DDR2_DQ41) ; also on sheet 114 115
M_C_DQ_42: CPU1.AA11(DDR2_DQ42) ; also on sheet 114 115
M_C_DQ_43: CPU1.AB8(DDR2_DQ43) ; also on sheet 114 115
M_C_DQ_44: CPU1.T10(DDR2_DQ44) ; also on sheet 114 115
M_C_DQ_45: CPU1.U11(DDR2_DQ45) ; also on sheet 114 115
M_C_DQ_46: CPU1.AA9(DDR2_DQ46) ; also on sheet 114 115
M_C_DQ_47: CPU1.Y8(DDR2_DQ47) ; also on sheet 114 115
M_C_DQ_48: CPU1.AE11(DDR2_DQ48) ; also on sheet 114 115
M_C_DQ_49: CPU1.AF12(DDR2_DQ49) ; also on sheet 114 115
M_C_DQ_50: CPU1.AK12(DDR2_DQ50) ; also on sheet 114 115
M_C_DQ_51: CPU1.AL13(DDR2_DQ51) ; also on sheet 114 115
M_C_DQ_52: CPU1.AG15(DDR2_DQ52) ; also on sheet 114 115
M_C_DQ_53: CPU1.AF14(DDR2_DQ53) ; also on sheet 114 115
M_C_DQ_54: CPU1.AK14(DDR2_DQ54) ; also on sheet 114 115
M_C_DQ_55: CPU1.AL15(DDR2_DQ55) ; also on sheet 114 115
M_C_DQ_56: CPU1.AG9(DDR2_DQ56) ; also on sheet 114 115
M_C_DQ_57: CPU1.AG7(DDR2_DQ57) ; also on sheet 114 115
M_C_DQ_58: CPU1.AK10(DDR2_DQ58) ; also on sheet 114 115
M_C_DQ_59: CPU1.AL9(DDR2_DQ59) ; also on sheet 114 115
M_C_DQ_60: CPU1.AE7(DDR2_DQ60) ; also on sheet 114 115
M_C_DQ_61: CPU1.AE9(DDR2_DQ61) ; also on sheet 114 115
M_C_DQ_62: CPU1.AK8(DDR2_DQ62) ; also on sheet 114 115
M_C_DQ_63: CPU1.AL7(DDR2_DQ63) ; also on sheet 114 115
M_C_DQS_DN_0: CPU1.W37(DDR2_DQS_DN0) ; also on sheet 114 115
M_C_DQS_DN_1: CPU1.V32(DDR2_DQS_DN1) ; also on sheet 114 115
M_C_DQS_DN_2: CPU1.AD32(DDR2_DQS_DN2) ; also on sheet 114 115
M_C_DQS_DN_3: CPU1.W25(DDR2_DQS_DN3) ; also on sheet 114 115
M_C_DQS_DN_4: CPU1.P8(DDR2_DQS_DN4) ; also on sheet 114 115
M_C_DQS_DN_5: CPU1.Y10(DDR2_DQS_DN5) ; also on sheet 114 115
M_C_DQS_DN_6: CPU1.AJ13(DDR2_DQS_DN6) ; also on sheet 114 115
M_C_DQS_DN_7: CPU1.AH8(DDR2_DQS_DN7) ; also on sheet 114 115
M_C_DQS_DN_8: CPU1.AE25(DDR2_DQS_DN8) ; also on sheet 114 115
M_C_DQS_DN_9: CPU1.AC37(DDR2_DQS_DN9) ; also on sheet 114 115
M_C_DQS_DN_10: CPU1.R33(DDR2_DQS_DN10) ; also on sheet 114 115
M_C_DQS_DN_11: CPU1.AA33(DDR2_DQS_DN11) ; also on sheet 114 115
M_C_DQS_DN_12: CPU1.T26(DDR2_DQS_DN12) ; also on sheet 114 115
M_C_DQS_DN_13: CPU1.L7(DDR2_DQS_DN13) ; also on sheet 114 115
M_C_DQS_DN_14: CPU1.W9(DDR2_DQS_DN14) ; also on sheet 114 115
M_C_DQS_DN_15: CPU1.AJ15(DDR2_DQS_DN15) ; also on sheet 114 115
M_C_DQS_DN_16: CPU1.AJ9(DDR2_DQS_DN16) ; also on sheet 114 115
M_C_DQS_DN_17: CPU1.AB26(DDR2_DQS_DN17) ; also on sheet 114 115
M_C_DQS_DP_0: CPU1.V38(DDR2_DQS_DP0) ; also on sheet 114 115
M_C_DQS_DP_1: CPU1.U31(DDR2_DQS_DP1) ; also on sheet 114 115
M_C_DQS_DP_2: CPU1.AB32(DDR2_DQS_DP2) ; also on sheet 114 115
M_C_DQS_DP_3: CPU1.U25(DDR2_DQS_DP3) ; also on sheet 114 115
M_C_DQS_DP_4: CPU1.N7(DDR2_DQS_DP4) ; also on sheet 114 115
M_C_DQS_DP_5: CPU1.AB10(DDR2_DQS_DP5) ; also on sheet 114 115
M_C_DQS_DP_6: CPU1.AH12(DDR2_DQS_DP6) ; also on sheet 114 115
M_C_DQS_DP_7: CPU1.AJ7(DDR2_DQS_DP7) ; also on sheet 114 115
M_C_DQS_DP_8: CPU1.AC25(DDR2_DQS_DP8) ; also on sheet 114 115
M_C_DQS_DP_9: CPU1.AB38(DDR2_DQS_DP9) ; also on sheet 114 115
M_C_DQS_DP_10: CPU1.T34(DDR2_DQS_DP10) ; also on sheet 114 115
M_C_DQS_DP_11: CPU1.AC33(DDR2_DQS_DP11) ; also on sheet 114 115
M_C_DQS_DP_12: CPU1.V26(DDR2_DQS_DP12) ; also on sheet 114 115
M_C_DQS_DP_13: CPU1.M8(DDR2_DQS_DP13) ; also on sheet 114 115
M_C_DQS_DP_14: CPU1.V8(DDR2_DQS_DP14) ; also on sheet 114 115
M_C_DQS_DP_15: CPU1.AH16(DDR2_DQS_DP15) ; also on sheet 114 115
M_C_DQS_DP_16: CPU1.AH10(DDR2_DQS_DP16) ; also on sheet 114 115
M_C_DQS_DP_17: CPU1.AD26(DDR2_DQS_DP17) ; also on sheet 114 115
M_C_ECC_0: CPU1.AC27(DDR2_ECC0) ; also on sheet 114 115
M_C_ECC_1: CPU1.AA27(DDR2_ECC1) ; also on sheet 114 115
M_C_ECC_2: CPU1.AC23(DDR2_ECC2) ; also on sheet 114 115
M_C_ECC_3: CPU1.AA23(DDR2_ECC3) ; also on sheet 114 115
M_C_ECC_4: CPU1.AD28(DDR2_ECC4) ; also on sheet 114 115
M_C_ECC_5: CPU1.AB28(DDR2_ECC5) ; also on sheet 114 115
M_C_ECC_6: CPU1.AD24(DDR2_ECC6) ; also on sheet 114 115
M_C_ECC_7: CPU1.AB24(DDR2_ECC7) ; also on sheet 114 115
M_C_MA_0: CPU1.L15(DDR2_MA0) ; also on sheet 114 115
M_C_MA_1: CPU1.M16(DDR2_MA1) ; also on sheet 114 115
M_C_MA_2: CPU1.T18(DDR2_MA2) ; also on sheet 114 115
M_C_MA_3: CPU1.L17(DDR2_MA3) ; also on sheet 114 115
M_C_MA_4: CPU1.R19(DDR2_MA4) ; also on sheet 114 115
M_C_MA_5: CPU1.P18(DDR2_MA5) ; also on sheet 114 115
M_C_MA_6: CPU1.M18(DDR2_MA6) ; also on sheet 114 115
M_C_MA_7: CPU1.U19(DDR2_MA7) ; also on sheet 114 115
M_C_MA_8: CPU1.L19(DDR2_MA8) ; also on sheet 114 115
M_C_MA_9: CPU1.P20(DDR2_MA9) ; also on sheet 114 115
M_C_MA_10: CPU1.AA15(DDR2_MA10) ; also on sheet 114 115
M_C_MA_11: CPU1.T20(DDR2_MA11) ; also on sheet 114 115
M_C_MA_12: CPU1.W21(DDR2_MA12) ; also on sheet 114 115
M_C_MA_13: CPU1.P12(DDR2_MA13) ; also on sheet 114 115
M_C_MA_14: CPU1.Y14(DDR2_MA14) ; also on sheet 114 115
M_C_MA_15: CPU1.R13(DDR2_MA15) ; also on sheet 114 115
M_C_MA_16: CPU1.P14(DDR2_MA16) ; also on sheet 114 115
M_C_MA_17: CPU1.T14(DDR2_MA17) ; also on sheet 114 115
M_C_ODT_0: CPU1.Y16(DDR2_ODT0) ; also on sheet 115
M_C_ODT_1: CPU1.W15(DDR2_ODT1) ; also on sheet 115
M_C_ODT_2: CPU1.R15(DDR2_ODT2) ; also on sheet 114
M_C_ODT_3: CPU1.AB14(DDR2_ODT3) ; also on sheet 114
M_C_PAR: CPU1.R17(DDR2_PAR) ; also on sheet 114 115
M_D_ACT_N: CPU1.L21(DDR3_ACT#) ; also on sheet 112 113
M_D_ALERT_N: CPU1.M22(DDR3_ALERT#) ; also on sheet 112 113
M_D_BA_0: CPU1.G13(DDR3_BA0) ; also on sheet 112 113
M_D_BA_1: CPU1.K14(DDR3_BA1) ; also on sheet 112 113
M_D_BG_0: CPU1.J21(DDR3_BG0) ; also on sheet 112 113
M_D_BG_1: CPU1.G21(DDR3_BG1) ; also on sheet 112 113
M_D_C_2: CPU1.J11(DDR3_CID2) ; also on sheet 112 113
M_D_CKE_0: CPU1.F22(DDR3_CKE0) ; also on sheet 113
M_D_CKE_1: CPU1.E21(DDR3_CKE1) ; also on sheet 113
M_D_CKE_2: CPU1.A21(DDR3_CKE2) ; also on sheet 112
M_D_CKE_3: CPU1.D22(DDR3_CKE3) ; also on sheet 112
M_D_CLK_DN_0: CPU1.C17(DDR3_CLK_DN0) ; also on sheet 113
M_D_CLK_DN_1: CPU1.D20(DDR3_CLK_DN1) ; also on sheet 112
M_D_CLK_DN_2: CPU1.D18(DDR3_CLK_DN2) ; also on sheet 113
M_D_CLK_DN_3: CPU1.C19(DDR3_CLK_DN3) ; also on sheet 112
M_D_CLK_DP_0: CPU1.A17(DDR3_CLK_DP0) ; also on sheet 113
M_D_CLK_DP_1: CPU1.B20(DDR3_CLK_DP1) ; also on sheet 112
M_D_CLK_DP_2: CPU1.B18(DDR3_CLK_DP2) ; also on sheet 113
M_D_CLK_DP_3: CPU1.A19(DDR3_CLK_DP3) ; also on sheet 112
M_D_CS_N_0: CPU1.B16(DDR3_CS0#) ; also on sheet 113
M_D_CS_N_1: CPU1.C15(DDR3_CS1#) ; also on sheet 113
M_D_CS_N_2: CPU1.F10(DDR3_CS2#/CID0) ; also on sheet 113
M_D_CS_N_3: CPU1.H10(DDR3_CS3#/CID1) ; also on sheet 113
M_D_CS_N_4: CPU1.A15(DDR3_CS4#) ; also on sheet 112
M_D_CS_N_5: CPU1.F14(DDR3_CS5#) ; also on sheet 112
M_D_CS_N_6: CPU1.G11(DDR3_CS6#/CID3) ; also on sheet 112
M_D_CS_N_7: CPU1.A11(DDR3_CS7#/CID4) ; also on sheet 112
M_D_DQ_0: CPU1.D38(DDR3_DQ0) ; also on sheet 112 113
M_D_DQ_1: CPU1.B38(DDR3_DQ1) ; also on sheet 112 113
M_D_DQ_2: CPU1.L37(DDR3_DQ2) ; also on sheet 112 113
M_D_DQ_3: CPU1.M38(DDR3_DQ3) ; also on sheet 112 113
M_D_DQ_4: CPU1.C39(DDR3_DQ4) ; also on sheet 112 113
M_D_DQ_5: CPU1.J39(DDR3_DQ5) ; also on sheet 112 113
M_D_DQ_6: CPU1.G37(DDR3_DQ6) ; also on sheet 112 113
M_D_DQ_7: CPU1.K38(DDR3_DQ7) ; also on sheet 112 113
M_D_DQ_8: CPU1.A35(DDR3_DQ8) ; also on sheet 112 113
M_D_DQ_9: CPU1.B34(DDR3_DQ9) ; also on sheet 112 113
M_D_DQ_10: CPU1.G31(DDR3_DQ10) ; also on sheet 112 113
M_D_DQ_11: CPU1.E31(DDR3_DQ11) ; also on sheet 112 113
M_D_DQ_12: CPU1.F34(DDR3_DQ12) ; also on sheet 112 113
M_D_DQ_13: CPU1.E35(DDR3_DQ13) ; also on sheet 112 113
M_D_DQ_14: CPU1.D32(DDR3_DQ14) ; also on sheet 112 113
M_D_DQ_15: CPU1.E33(DDR3_DQ15) ; also on sheet 112 113
M_D_DQ_16: CPU1.K34(DDR3_DQ16) ; also on sheet 112 113
M_D_DQ_17: CPU1.M34(DDR3_DQ17) ; also on sheet 112 113
M_D_DQ_18: CPU1.K30(DDR3_DQ18) ; also on sheet 112 113
M_D_DQ_19: CPU1.M30(DDR3_DQ19) ; also on sheet 112 113
M_D_DQ_20: CPU1.J35(DDR3_DQ20) ; also on sheet 112 113
M_D_DQ_21: CPU1.L35(DDR3_DQ21) ; also on sheet 112 113
M_D_DQ_22: CPU1.L31(DDR3_DQ22) ; also on sheet 112 113
M_D_DQ_23: CPU1.N31(DDR3_DQ23) ; also on sheet 112 113
M_D_DQ_24: CPU1.F28(DDR3_DQ24) ; also on sheet 112 113
M_D_DQ_25: CPU1.E27(DDR3_DQ25) ; also on sheet 112 113
M_D_DQ_26: CPU1.F24(DDR3_DQ26) ; also on sheet 112 113
M_D_DQ_27: CPU1.E23(DDR3_DQ27) ; also on sheet 112 113
M_D_DQ_28: CPU1.G29(DDR3_DQ28) ; also on sheet 112 113
M_D_DQ_29: CPU1.E29(DDR3_DQ29) ; also on sheet 112 113
M_D_DQ_30: CPU1.C25(DDR3_DQ30) ; also on sheet 112 113
M_D_DQ_31: CPU1.B24(DDR3_DQ31) ; also on sheet 112 113
M_D_DQ_32: CPU1.K4(DDR3_DQ32) ; also on sheet 112 113
M_D_DQ_33: CPU1.H4(DDR3_DQ33) ; also on sheet 112 113
M_D_DQ_34: CPU1.J1(DDR3_DQ34) ; also on sheet 112 113
M_D_DQ_35: CPU1.L1(DDR3_DQ35) ; also on sheet 112 113
M_D_DQ_36: CPU1.P4(DDR3_DQ36) ; also on sheet 112 113
M_D_DQ_37: CPU1.N3(DDR3_DQ37) ; also on sheet 112 113
M_D_DQ_38: CPU1.K2(DDR3_DQ38) ; also on sheet 112 113
M_D_DQ_39: CPU1.R3(DDR3_DQ39) ; also on sheet 112 113
M_D_DQ_40: CPU1.E9(DDR3_DQ40) ; also on sheet 112 113
M_D_DQ_41: CPU1.F8(DDR3_DQ41) ; also on sheet 112 113
M_D_DQ_42: CPU1.E5(DDR3_DQ42) ; also on sheet 112 113
M_D_DQ_43: CPU1.F6(DDR3_DQ43) ; also on sheet 112 113
M_D_DQ_44: CPU1.C9(DDR3_DQ44) ; also on sheet 112 113
M_D_DQ_45: CPU1.A9(DDR3_DQ45) ; also on sheet 112 113
M_D_DQ_46: CPU1.D6(DDR3_DQ46) ; also on sheet 112 113
M_D_DQ_47: CPU1.G7(DDR3_DQ47) ; also on sheet 112 113
M_D_DQ_48: CPU1.AG3(DDR3_DQ48) ; also on sheet 112 113
M_D_DQ_49: CPU1.AG1(DDR3_DQ49) ; also on sheet 112 113
M_D_DQ_50: CPU1.AL3(DDR3_DQ50) ; also on sheet 112 113
M_D_DQ_51: CPU1.AL5(DDR3_DQ51) ; also on sheet 112 113
M_D_DQ_52: CPU1.AG5(DDR3_DQ52) ; also on sheet 112 113
M_D_DQ_53: CPU1.AE3(DDR3_DQ53) ; also on sheet 112 113
M_D_DQ_54: CPU1.AJ3(DDR3_DQ54) ; also on sheet 112 113
M_D_DQ_55: CPU1.AL1(DDR3_DQ55) ; also on sheet 112 113
M_D_DQ_56: CPU1.V4(DDR3_DQ56) ; also on sheet 112 113
M_D_DQ_57: CPU1.W3(DDR3_DQ57) ; also on sheet 112 113
M_D_DQ_58: CPU1.AC5(DDR3_DQ58) ; also on sheet 112 113
M_D_DQ_59: CPU1.AE5(DDR3_DQ59) ; also on sheet 112 113
M_D_DQ_60: CPU1.U5(DDR3_DQ60) ; also on sheet 112 113
M_D_DQ_61: CPU1.V6(DDR3_DQ61) ; also on sheet 112 113
M_D_DQ_62: CPU1.AC3(DDR3_DQ62) ; also on sheet 112 113
M_D_DQ_63: CPU1.AB6(DDR3_DQ63) ; also on sheet 112 113
M_D_DQS_DN_0: CPU1.C37(DDR3_DQS_DN0) ; also on sheet 112 113
M_D_DQS_DN_1: CPU1.A33(DDR3_DQS_DN1) ; also on sheet 112 113
M_D_DQS_DN_2: CPU1.K32(DDR3_DQS_DN2) ; also on sheet 112 113
M_D_DQS_DN_3: CPU1.G25(DDR3_DQS_DN3) ; also on sheet 112 113
M_D_DQS_DN_4: CPU1.G3(DDR3_DQS_DN4) ; also on sheet 112 113
M_D_DQS_DN_5: CPU1.C7(DDR3_DQS_DN5) ; also on sheet 112 113
M_D_DQS_DN_6: CPU1.AJ1(DDR3_DQS_DN6) ; also on sheet 112 113
M_D_DQS_DN_7: CPU1.AA5(DDR3_DQS_DN7) ; also on sheet 112 113
M_D_DQS_DN_8: CPU1.N25(DDR3_DQS_DN8) ; also on sheet 112 113
M_D_DQS_DN_9: CPU1.H38(DDR3_DQS_DN9) ; also on sheet 112 113
M_D_DQS_DN_10: CPU1.D34(DDR3_DQS_DN10) ; also on sheet 112 113
M_D_DQS_DN_11: CPU1.L33(DDR3_DQS_DN11) ; also on sheet 112 113
M_D_DQS_DN_12: CPU1.D26(DDR3_DQS_DN12) ; also on sheet 112 113
M_D_DQS_DN_13: CPU1.L3(DDR3_DQS_DN13) ; also on sheet 112 113
M_D_DQS_DN_14: CPU1.D8(DDR3_DQS_DN14) ; also on sheet 112 113
M_D_DQS_DN_15: CPU1.AJ5(DDR3_DQS_DN15) ; also on sheet 112 113
M_D_DQS_DN_16: CPU1.W5(DDR3_DQS_DN16) ; also on sheet 112 113
M_D_DQS_DN_17: CPU1.K26(DDR3_DQS_DN17) ; also on sheet 112 113
M_D_DQS_DP_0: CPU1.E37(DDR3_DQS_DP0) ; also on sheet 112 113
M_D_DQS_DP_1: CPU1.B32(DDR3_DQS_DP1) ; also on sheet 112 113
M_D_DQS_DP_2: CPU1.M32(DDR3_DQS_DP2) ; also on sheet 112 113
M_D_DQS_DP_3: CPU1.E25(DDR3_DQS_DP3) ; also on sheet 112 113
M_D_DQS_DP_4: CPU1.H2(DDR3_DQS_DP4) ; also on sheet 112 113
M_D_DQS_DP_5: CPU1.E7(DDR3_DQS_DP5) ; also on sheet 112 113
M_D_DQS_DP_6: CPU1.AK2(DDR3_DQS_DP6) ; also on sheet 112 113
M_D_DQS_DP_7: CPU1.AB4(DDR3_DQS_DP7) ; also on sheet 112 113
M_D_DQS_DP_8: CPU1.L25(DDR3_DQS_DP8) ; also on sheet 112 113
M_D_DQS_DP_9: CPU1.F38(DDR3_DQS_DP9) ; also on sheet 112 113
M_D_DQS_DP_10: CPU1.C35(DDR3_DQS_DP10) ; also on sheet 112 113
M_D_DQS_DP_11: CPU1.J33(DDR3_DQS_DP11) ; also on sheet 112 113
M_D_DQS_DP_12: CPU1.F26(DDR3_DQS_DP12) ; also on sheet 112 113
M_D_DQS_DP_13: CPU1.M4(DDR3_DQS_DP13) ; also on sheet 112 113
M_D_DQS_DP_14: CPU1.B8(DDR3_DQS_DP14) ; also on sheet 112 113
M_D_DQS_DP_15: CPU1.AH4(DDR3_DQS_DP15) ; also on sheet 112 113
M_D_DQS_DP_16: CPU1.Y6(DDR3_DQS_DP16) ; also on sheet 112 113
M_D_DQS_DP_17: CPU1.M26(DDR3_DQS_DP17) ; also on sheet 112 113
M_D_ECC_0: CPU1.L27(DDR3_ECC0) ; also on sheet 112 113
M_D_ECC_1: CPU1.J27(DDR3_ECC1) ; also on sheet 112 113
M_D_ECC_2: CPU1.L23(DDR3_ECC2) ; also on sheet 112 113
M_D_ECC_3: CPU1.J23(DDR3_ECC3) ; also on sheet 112 113
M_D_ECC_4: CPU1.K28(DDR3_ECC4) ; also on sheet 112 113
M_D_ECC_5: CPU1.M28(DDR3_ECC5) ; also on sheet 112 113
M_D_ECC_6: CPU1.M24(DDR3_ECC6) ; also on sheet 112 113
M_D_ECC_7: CPU1.K24(DDR3_ECC7) ; also on sheet 112 113
M_D_MA_0: CPU1.G15(DDR3_MA0) ; also on sheet 112 113
M_D_MA_1: CPU1.K16(DDR3_MA1) ; also on sheet 112 113
M_D_MA_2: CPU1.F16(DDR3_MA2) ; also on sheet 112 113
M_D_MA_3: CPU1.G17(DDR3_MA3) ; also on sheet 112 113
M_D_MA_4: CPU1.J17(DDR3_MA4) ; also on sheet 112 113
M_D_MA_5: CPU1.K18(DDR3_MA5) ; also on sheet 112 113
M_D_MA_6: CPU1.F18(DDR3_MA6) ; also on sheet 112 113
M_D_MA_7: CPU1.J19(DDR3_MA7) ; also on sheet 112 113
M_D_MA_8: CPU1.G19(DDR3_MA8) ; also on sheet 112 113
M_D_MA_9: CPU1.F20(DDR3_MA9) ; also on sheet 112 113
M_D_MA_10: CPU1.L13(DDR3_MA10) ; also on sheet 112 113
M_D_MA_11: CPU1.K20(DDR3_MA11) ; also on sheet 112 113
M_D_MA_12: CPU1.M20(DDR3_MA12) ; also on sheet 112 113
M_D_MA_13: CPU1.M12(DDR3_MA13) ; also on sheet 112 113
M_D_MA_14: CPU1.K12(DDR3_MA14) ; also on sheet 112 113
M_D_MA_15: CPU1.F12(DDR3_MA15) ; also on sheet 112 113
M_D_MA_16: CPU1.J13(DDR3_MA16) ; also on sheet 112 113
M_D_MA_17: CPU1.L11(DDR3_MA17) ; also on sheet 112 113
M_D_ODT_0: CPU1.D16(DDR3_ODT0) ; also on sheet 113
M_D_ODT_1: CPU1.A13(DDR3_ODT1) ; also on sheet 113
M_D_ODT_2: CPU1.D14(DDR3_ODT2) ; also on sheet 112
M_D_ODT_3: CPU1.D12(DDR3_ODT3) ; also on sheet 112
M_D_PAR: CPU1.J15(DDR3_PAR) ; also on sheet 112 113
P3E_CPU0_PE1_RISER1_RX_DN_0: CPU1.C51(PE1A_RX_DN0) ; also on sheet 94
P3E_CPU0_PE1_RISER1_RX_DN_1: CPU1.D52(PE1A_RX_DN1) ; also on sheet 94
P3E_CPU0_PE1_RISER1_RX_DN_2: CPU1.D54(PE1A_RX_DN2) ; also on sheet 94
P3E_CPU0_PE1_RISER1_RX_DN_3: CPU1.E55(PE1A_RX_DN3) ; also on sheet 94
P3E_CPU0_PE1_RISER1_RX_DN_4: CPU1.J53(PE1B_RX_DN4) ; also on sheet 94
P3E_CPU0_PE1_RISER1_RX_DN_5: CPU1.K54(PE1B_RX_DN5) ; also on sheet 94
P3E_CPU0_PE1_RISER1_RX_DN_6: CPU1.J57(PE1B_RX_DN6) ; also on sheet 94
P3E_CPU0_PE1_RISER1_RX_DN_7: CPU1.K56(PE1B_RX_DN7) ; also on sheet 94
P3E_CPU0_PE1_RISER1_RX_DP_0: CPU1.E51(PE1A_RX_DP0) ; also on sheet 94
P3E_CPU0_PE1_RISER1_RX_DP_1: CPU1.F52(PE1A_RX_DP1) ; also on sheet 94
P3E_CPU0_PE1_RISER1_RX_DP_2: CPU1.F54(PE1A_RX_DP2) ; also on sheet 94
P3E_CPU0_PE1_RISER1_RX_DP_3: CPU1.G55(PE1A_RX_DP3) ; also on sheet 94
P3E_CPU0_PE1_RISER1_RX_DP_4: CPU1.L53(PE1B_RX_DP4) ; also on sheet 94
P3E_CPU0_PE1_RISER1_RX_DP_5: CPU1.M54(PE1B_RX_DP5) ; also on sheet 94
P3E_CPU0_PE1_RISER1_RX_DP_6: CPU1.L57(PE1B_RX_DP6) ; also on sheet 94
P3E_CPU0_PE1_RISER1_RX_DP_7: CPU1.M56(PE1B_RX_DP7) ; also on sheet 94
P3E_CPU0_PE1_RISER1_TX_C_DN_0: C369.2 ; also on sheet 94
P3E_CPU0_PE1_RISER1_TX_C_DN_1: C368.2 ; also on sheet 94
P3E_CPU0_PE1_RISER1_TX_C_DN_2: C367.2 ; also on sheet 94
P3E_CPU0_PE1_RISER1_TX_C_DN_3: C366.2 ; also on sheet 94
P3E_CPU0_PE1_RISER1_TX_C_DN_4: C360.2 ; also on sheet 94
P3E_CPU0_PE1_RISER1_TX_C_DN_5: C359.2 ; also on sheet 94
P3E_CPU0_PE1_RISER1_TX_C_DN_6: C322.2 ; also on sheet 94
P3E_CPU0_PE1_RISER1_TX_C_DN_7: C321.2 ; also on sheet 94
P3E_CPU0_PE1_RISER1_TX_C_DP_0: C365.2 ; also on sheet 94
P3E_CPU0_PE1_RISER1_TX_C_DP_1: C364.2 ; also on sheet 94
P3E_CPU0_PE1_RISER1_TX_C_DP_2: C362.2 ; also on sheet 94
P3E_CPU0_PE1_RISER1_TX_C_DP_3: C361.2 ; also on sheet 94
P3E_CPU0_PE1_RISER1_TX_C_DP_4: C320.2 ; also on sheet 94
P3E_CPU0_PE1_RISER1_TX_C_DP_5: C276.2 ; also on sheet 94
P3E_CPU0_PE1_RISER1_TX_C_DP_6: C275.2 ; also on sheet 94
P3E_CPU0_PE1_RISER1_TX_C_DP_7: C274.2 ; also on sheet 94
P3E_CPU0_PE1_RISER1_TX_DN_0: C369.1 CPU1.H42(PE1A_TX_DN0)
P3E_CPU0_PE1_RISER1_TX_DN_1: C368.1 CPU1.J43(PE1A_TX_DN1)
P3E_CPU0_PE1_RISER1_TX_DN_2: C367.1 CPU1.H44(PE1A_TX_DN2)
P3E_CPU0_PE1_RISER1_TX_DN_3: C366.1 CPU1.J45(PE1A_TX_DN3)
P3E_CPU0_PE1_RISER1_TX_DN_4: C360.1 CPU1.H46(PE1B_TX_DN4)
P3E_CPU0_PE1_RISER1_TX_DN_5: C359.1 CPU1.J47(PE1B_TX_DN5)
P3E_CPU0_PE1_RISER1_TX_DN_6: C322.1 CPU1.H48(PE1B_TX_DN6)
P3E_CPU0_PE1_RISER1_TX_DN_7: C321.1 CPU1.J49(PE1B_TX_DN7)
P3E_CPU0_PE1_RISER1_TX_DP_0: C365.1 CPU1.K42(PE1A_TX_DP0)
P3E_CPU0_PE1_RISER1_TX_DP_1: C364.1 CPU1.L43(PE1A_TX_DP1)
P3E_CPU0_PE1_RISER1_TX_DP_2: C362.1 CPU1.K44(PE1A_TX_DP2)
P3E_CPU0_PE1_RISER1_TX_DP_3: C361.1 CPU1.L45(PE1A_TX_DP3)
P3E_CPU0_PE1_RISER1_TX_DP_4: C320.1 CPU1.K46(PE1B_TX_DP4)
P3E_CPU0_PE1_RISER1_TX_DP_5: C276.1 CPU1.L47(PE1B_TX_DP5)
P3E_CPU0_PE1_RISER1_TX_DP_6: C275.1 CPU1.K48(PE1B_TX_DP6)
P3E_CPU0_PE1_RISER1_TX_DP_7: C274.1 CPU1.L49(PE1B_TX_DP7)
P3E_CPU0_PE2_RISER1_RX_DN_0: CPU1.L55(PE2A_RX_DN0) ; also on sheet 94
P3E_CPU0_PE2_RISER1_RX_DN_1: CPU1.T54(PE2A_RX_DN1) ; also on sheet 94
P3E_CPU0_PE2_RISER1_RX_DN_2: CPU1.T56(PE2A_RX_DN2) ; also on sheet 94
P3E_CPU0_PE2_RISER1_RX_DN_3: CPU1.U55(PE2A_RX_DN3) ; also on sheet 94
P3E_CPU0_PE2_RISER1_RX_DN_4: CPU1.AB54(PE2B_RX_DN4) ; also on sheet 94
P3E_CPU0_PE2_RISER1_RX_DN_5: CPU1.AB56(PE2B_RX_DN5) ; also on sheet 94
P3E_CPU0_PE2_RISER1_RX_DN_6: CPU1.AC55(PE2B_RX_DN6) ; also on sheet 94
P3E_CPU0_PE2_RISER1_RX_DN_7: CPU1.AE57(PE2B_RX_DN7) ; also on sheet 94
P3E_CPU0_PE2_RISER1_RX_DN_8: CPU1.AH56(PE2C_RX_DN8) ; also on sheet 94
P3E_CPU0_PE2_RISER1_RX_DN_9: CPU1.AK58(PE2C_RX_DN9) ; also on sheet 94
P3E_CPU0_PE2_RISER1_RX_DN_10: CPU1.AJ57(PE2C_RX_DN10) ; also on sheet 94
P3E_CPU0_PE2_RISER1_RX_DN_11: CPU1.AR57(PE2C_RX_DN11) ; also on sheet 94
P3E_CPU0_PE2_RISER1_RX_DN_12: CPU1.AT58(PE2D_RX_DN12) ; also on sheet 94
P3E_CPU0_PE2_RISER1_RX_DN_13: CPU1.AP56(PE2D_RX_DN13) ; also on sheet 94
P3E_CPU0_PE2_RISER1_RX_DN_14: CPU1.AY58(PE2D_RX_DN14) ; also on sheet 94
P3E_CPU0_PE2_RISER1_RX_DN_15: CPU1.AY56(PE2D_RX_DN15) ; also on sheet 94
P3E_CPU0_PE2_RISER1_RX_DP_0: CPU1.N55(PE2A_RX_DP0) ; also on sheet 94
P3E_CPU0_PE2_RISER1_RX_DP_1: CPU1.V54(PE2A_RX_DP1) ; also on sheet 94
P3E_CPU0_PE2_RISER1_RX_DP_2: CPU1.V56(PE2A_RX_DP2) ; also on sheet 94
P3E_CPU0_PE2_RISER1_RX_DP_3: CPU1.W55(PE2A_RX_DP3) ; also on sheet 94
P3E_CPU0_PE2_RISER1_RX_DP_4: CPU1.AD54(PE2B_RX_DP4) ; also on sheet 94
P3E_CPU0_PE2_RISER1_RX_DP_5: CPU1.AD56(PE2B_RX_DP5) ; also on sheet 94
P3E_CPU0_PE2_RISER1_RX_DP_6: CPU1.AE55(PE2B_RX_DP6) ; also on sheet 94
P3E_CPU0_PE2_RISER1_RX_DP_7: CPU1.AF58(PE2B_RX_DP7) ; also on sheet 94
P3E_CPU0_PE2_RISER1_RX_DP_8: CPU1.AK56(PE2C_RX_DP8) ; also on sheet 94
P3E_CPU0_PE2_RISER1_RX_DP_9: CPU1.AM58(PE2C_RX_DP9) ; also on sheet 94
P3E_CPU0_PE2_RISER1_RX_DP_10: CPU1.AL57(PE2C_RX_DP10) ; also on sheet 94
P3E_CPU0_PE2_RISER1_RX_DP_11: CPU1.AU57(PE2C_RX_DP11) ; also on sheet 94
P3E_CPU0_PE2_RISER1_RX_DP_12: CPU1.AV58(PE2D_RX_DP12) ; also on sheet 94
P3E_CPU0_PE2_RISER1_RX_DP_13: CPU1.AT56(PE2D_RX_DP13) ; also on sheet 94
P3E_CPU0_PE2_RISER1_RX_DP_14: CPU1.BA57(PE2D_RX_DP14) ; also on sheet 94
P3E_CPU0_PE2_RISER1_RX_DP_15: CPU1.BB56(PE2D_RX_DP15) ; also on sheet 94
P3E_CPU0_PE2_RISER1_TX_DN_0: CPU1.AN49(PE2A_TX_DN0) ; also on sheet 94
P3E_CPU0_PE2_RISER1_TX_DN_1: CPU1.AM50(PE2A_TX_DN1) ; also on sheet 94
P3E_CPU0_PE2_RISER1_TX_DN_2: CPU1.AN51(PE2A_TX_DN2) ; also on sheet 94
P3E_CPU0_PE2_RISER1_TX_DN_3: CPU1.AM52(PE2A_TX_DN3) ; also on sheet 94
P3E_CPU0_PE2_RISER1_TX_DN_4: CPU1.AG53(PE2B_TX_DN4) ; also on sheet 94
P3E_CPU0_PE2_RISER1_TX_DN_5: CPU1.AH54(PE2B_TX_DN5) ; also on sheet 94
P3E_CPU0_PE2_RISER1_TX_DN_6: CPU1.AN53(PE2B_TX_DN6) ; also on sheet 94
P3E_CPU0_PE2_RISER1_TX_DN_7: CPU1.AP54(PE2B_TX_DN7) ; also on sheet 94
P3E_CPU0_PE2_RISER1_TX_DN_8: CPU1.AV52(PE2C_TX_DN8) ; also on sheet 94
P3E_CPU0_PE2_RISER1_TX_DN_9: CPU1.AW53(PE2C_TX_DN9) ; also on sheet 94
P3E_CPU0_PE2_RISER1_TX_DN_10: CPU1.AY54(PE2C_TX_DN10) ; also on sheet 94
P3E_CPU0_PE2_RISER1_TX_DN_11: CPU1.AW51(PE2C_TX_DN11) ; also on sheet 94
P3E_CPU0_PE2_RISER1_TX_DN_12: CPU1.AV50(PE2D_TX_DN12) ; also on sheet 94
P3E_CPU0_PE2_RISER1_TX_DN_13: CPU1.AW49(PE2D_TX_DN13) ; also on sheet 94
P3E_CPU0_PE2_RISER1_TX_DN_14: CPU1.AV48(PE2D_TX_DN14) ; also on sheet 94
P3E_CPU0_PE2_RISER1_TX_DN_15: CPU1.AW47(PE2D_TX_DN15) ; also on sheet 94
P3E_CPU0_PE2_RISER1_TX_DP_0: CPU1.AR49(PE2A_TX_DP0) ; also on sheet 94
P3E_CPU0_PE2_RISER1_TX_DP_1: CPU1.AP50(PE2A_TX_DP1) ; also on sheet 94
P3E_CPU0_PE2_RISER1_TX_DP_2: CPU1.AR51(PE2A_TX_DP2) ; also on sheet 94
P3E_CPU0_PE2_RISER1_TX_DP_3: CPU1.AP52(PE2A_TX_DP3) ; also on sheet 94
P3E_CPU0_PE2_RISER1_TX_DP_4: CPU1.AJ53(PE2B_TX_DP4) ; also on sheet 94
P3E_CPU0_PE2_RISER1_TX_DP_5: CPU1.AK54(PE2B_TX_DP5) ; also on sheet 94
P3E_CPU0_PE2_RISER1_TX_DP_6: CPU1.AR53(PE2B_TX_DP6) ; also on sheet 94
P3E_CPU0_PE2_RISER1_TX_DP_7: CPU1.AT54(PE2B_TX_DP7) ; also on sheet 94
P3E_CPU0_PE2_RISER1_TX_DP_8: CPU1.AY52(PE2C_TX_DP8) ; also on sheet 94
P3E_CPU0_PE2_RISER1_TX_DP_9: CPU1.BA53(PE2C_TX_DP9) ; also on sheet 94
P3E_CPU0_PE2_RISER1_TX_DP_10: CPU1.BB54(PE2C_TX_DP10) ; also on sheet 94
P3E_CPU0_PE2_RISER1_TX_DP_11: CPU1.BA51(PE2C_TX_DP11) ; also on sheet 94
P3E_CPU0_PE2_RISER1_TX_DP_12: CPU1.AY50(PE2D_TX_DP12) ; also on sheet 94
P3E_CPU0_PE2_RISER1_TX_DP_13: CPU1.BA49(PE2D_TX_DP13) ; also on sheet 94
P3E_CPU0_PE2_RISER1_TX_DP_14: CPU1.AY48(PE2D_TX_DP14) ; also on sheet 94
P3E_CPU0_PE2_RISER1_TX_DP_15: CPU1.BA47(PE2D_TX_DP15) ; also on sheet 94

Not connected (* = marked no-connect by the designer): CPU1 AB22(DDR2_CKE4)* AD14(DDR2_ODT5)* AD18(DDR2_CS8#)* AD22(DDR2_CKE5)* AE17(DDR2_ODT4)* B12(DDR3_CS9#)* B14(DDR3_CS8#)* B22(DDR3_CKE4)* CY16(DDR1_CKE4)* DA15(DDR1_CKE5)* DA25(DDR1_ODT4)* DD26(DDR1_ODT5)* DF24(DDR1_CS8#)* DF26(DDR1_CS9#)* E11(DDR3_ODT5)* E13(DDR3_ODT4)* K22(DDR3_CKE5)* T12(DDR2_CS9#)*

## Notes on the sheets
sheet 132
- CPU1 - PCIE (2A-2D)
- To PCIe x24 slot
- To PCIe x24 slot
- CPU1 - PCIE (2A-2D)
sheet 133
- CPU1 - DMI & PCIE (1A-1B)
- Place close to CPU0
- To PCIe x24 slot
- To PCIe x24 slot
sheet 134
- CPU0 - DDR4 (CHANNEL D)
- FAB1 REV003 20150318
sheet 135
- CPU1 - DDR4 (CHANNEL C)
- FAB1 REV003 20150318
sheet 136
- CPU0 - DDR4 (CHANNEL B)
- RAS_N/MA[16]
- CAS_N/MA[15]
- WE_N/MA[14]
- FAB1 REV003 20150318
- Chip ID : Used to select a single die out of the stack
- of a 3DS device.
- CID[4:3] are MUXed with CS_N[7:6], respectively.
- CID[1:0] are MUXed with CS_N[3:2], respectively.
- Activate. When asserted, indicated MA[16:14] are command signals.
